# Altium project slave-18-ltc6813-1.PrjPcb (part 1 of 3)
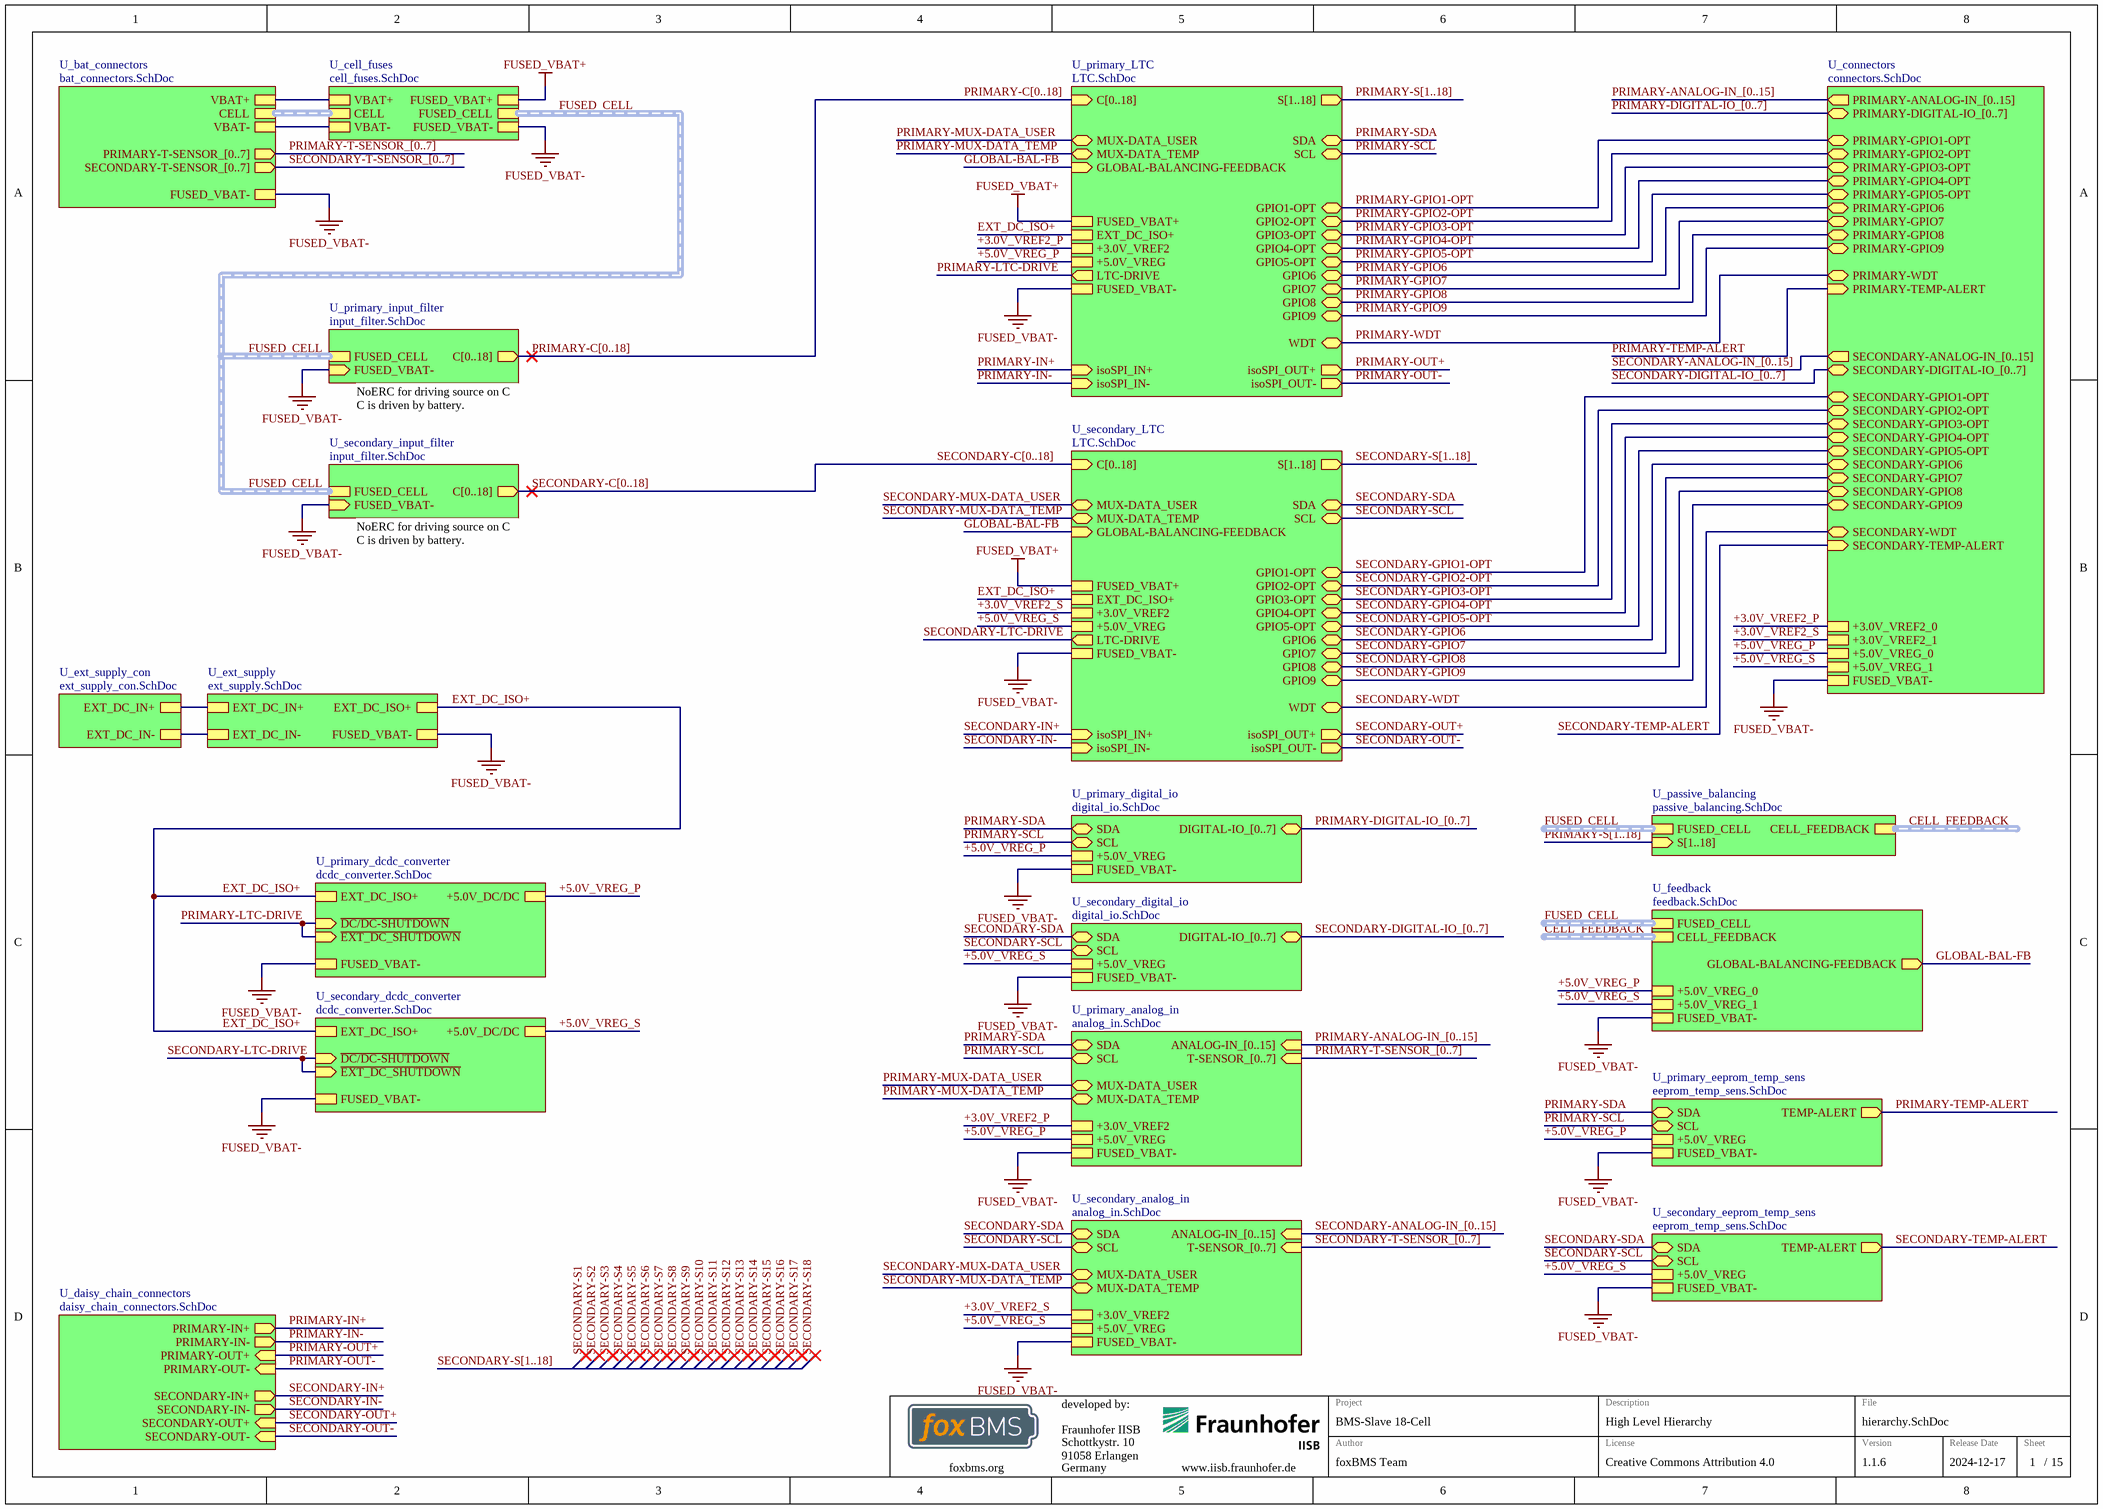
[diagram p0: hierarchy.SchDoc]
GlobalDate: 2024-12-17; GlobalLicense: Creative Commons Attribution 4.0; GlobalProject: BMS-Slave 18-Cell; GlobalVersion: 1.1.6
15 sheets, 591 parts. Net scope: strictly hierarchical (ports join the sheet entries above them; power ports are local).
Board file: slave.PcbDoc
Sheets:
  hierarchy.SchDoc
    U_cell_fuses = cell_fuses.SchDoc
    U_primary_input_filter = input_filter.SchDoc
    U_secondary_input_filter = input_filter.SchDoc
    U_ext_supply = ext_supply.SchDoc
    U_connectors = connectors.SchDoc
    U_feedback = feedback.SchDoc
    U_passive_balancing = passive_balancing.SchDoc
    U_primary_LTC = LTC.SchDoc
    U_secondary_digital_io = digital_io.SchDoc
    U_secondary_eeprom_temp_sens = eeprom_temp_sens.SchDoc
    U_secondary_analog_in = analog_in.SchDoc
    U_daisy_chain_connectors = daisy_chain_connectors.SchDoc
    U_ext_supply_con = ext_supply_con.SchDoc
    U_bat_connectors = bat_connectors.SchDoc
    U_primary_dcdc_converter = dcdc_converter.SchDoc
    U_secondary_dcdc_converter = dcdc_converter.SchDoc
    U_secondary_LTC = LTC.SchDoc
    U_primary_digital_io = digital_io.SchDoc
    U_primary_eeprom_temp_sens = eeprom_temp_sens.SchDoc
    U_primary_analog_in = analog_in.SchDoc

## Sheet hierarchy.SchDoc
size A3; SheetNumber: 1; SheetTotal: 15; SheetDescription: High Level Hierarchy

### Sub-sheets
U_bat_connectors = bat_connectors.SchDoc: CELL (harness CELL_VOLTAGES), PRIMARY-T-SENSOR_[0..7] (out), SECONDARY-T-SENSOR_[0..7] (out), VBAT+, VBAT-, FUSED_VBAT-
U_cell_fuses = cell_fuses.SchDoc: FUSED_CELL (harness CELL_VOLTAGES), CELL (harness CELL_VOLTAGES), VBAT+, VBAT-, FUSED_VBAT+, FUSED_VBAT-
U_connectors = connectors.SchDoc: PRIMARY-WDT (bidir), SECONDARY-WDT (bidir), PRIMARY-GPIO1-OPT (bidir), PRIMARY-GPIO2-OPT (bidir), PRIMARY-GPIO3-OPT (bidir), PRIMARY-GPIO4-OPT (bidir), PRIMARY-GPIO5-OPT (bidir), SECONDARY-GPIO1-OPT (bidir), SECONDARY-GPIO2-OPT (bidir), SECONDARY-GPIO3-OPT (bidir), SECONDARY-GPIO4-OPT (bidir), SECONDARY-GPIO5-OPT (bidir), PRIMARY-TEMP-ALERT (in), SECONDARY-TEMP-ALERT (in), SECONDARY-DIGITAL-IO_[0..7] (bidir), PRIMARY-DIGITAL-IO_[0..7] (bidir), PRIMARY-ANALOG-IN_[0..15] (out), SECONDARY-ANALOG-IN_[0..15] (out), PRIMARY-GPIO9 (bidir), PRIMARY-GPIO7 (bidir), PRIMARY-GPIO6 (bidir), PRIMARY-GPIO8 (bidir), SECONDARY-GPIO9 (bidir), SECONDARY-GPIO8 (bidir), SECONDARY-GPIO7 (bidir), SECONDARY-GPIO6 (bidir), +3.0V_VREF2_1, +5.0V_VREG_1, +3.0V_VREF2_0, FUSED_VBAT-, +5.0V_VREG_0
U_daisy_chain_connectors = daisy_chain_connectors.SchDoc: SECONDARY-IN+ (out), SECONDARY-IN- (out), SECONDARY-OUT+ (in), SECONDARY-OUT- (in), PRIMARY-IN+ (out), PRIMARY-IN- (out), PRIMARY-OUT- (in), PRIMARY-OUT+ (in)
U_ext_supply = ext_supply.SchDoc: EXT_DC_IN+, EXT_DC_IN-, EXT_DC_ISO+, FUSED_VBAT-
U_ext_supply_con = ext_supply_con.SchDoc: EXT_DC_IN+, EXT_DC_IN-
U_feedback = feedback.SchDoc: GLOBAL-BALANCING-FEEDBACK (out), CELL_FEEDBACK (harness CELL_FEEDBACK), FUSED_CELL (harness CELL_VOLTAGES), +5.0V_VREG_1, +5.0V_VREG_0, FUSED_VBAT-
U_passive_balancing = passive_balancing.SchDoc: FUSED_CELL (harness CELL_VOLTAGES), S[1..18] (in), CELL_FEEDBACK (harness CELL_FEEDBACK)
U_primary_analog_in = analog_in.SchDoc: MUX-DATA_TEMP (bidir), MUX-DATA_USER (bidir), ANALOG-IN_[0..15] (in), T-SENSOR_[0..7] (in), SCL (bidir), SDA (bidir), +5.0V_VREG, FUSED_VBAT-, +3.0V_VREF2
U_primary_dcdc_converter = dcdc_converter.SchDoc: +5.0V_DC/DC, FUSED_VBAT-, ~{DC/DC-SHUTDOWN} (in), EXT_DC_ISO+, ~{EXT_DC_SHUTDOWN} (in)
U_primary_digital_io = digital_io.SchDoc: SCL (bidir), SDA (bidir), DIGITAL-IO_[0..7] (bidir), +5.0V_VREG, FUSED_VBAT-
U_primary_eeprom_temp_sens = eeprom_temp_sens.SchDoc: TEMP-ALERT (out), SDA (bidir), SCL (bidir), FUSED_VBAT-, +5.0V_VREG
U_primary_input_filter = input_filter.SchDoc: FUSED_CELL (harness CELL_VOLTAGES), C[0..18] (out), FUSED_VBAT- (in)
U_primary_LTC = LTC.SchDoc: isoSPI_IN- (in), isoSPI_IN+ (in), isoSPI_OUT- (out), isoSPI_OUT+ (out), GPIO5-OPT (bidir), GPIO4-OPT (bidir), MUX-DATA_USER (bidir), GPIO1-OPT (bidir), SCL (bidir), GPIO2-OPT (bidir), MUX-DATA_TEMP (bidir), GPIO3-OPT (bidir), GLOBAL-BALANCING-FEEDBACK (in), SDA (bidir), EXT_DC_ISO+, C[0..18] (in), S[1..18] (out), WDT (bidir), GPIO8 (bidir), GPIO7 (bidir), GPIO9 (bidir), GPIO6 (bidir), FUSED_VBAT+, FUSED_VBAT-, +5.0V_VREG, +3.0V_VREF2, LTC-DRIVE (out)
U_secondary_analog_in = analog_in.SchDoc: MUX-DATA_TEMP (bidir), MUX-DATA_USER (bidir), ANALOG-IN_[0..15] (in), T-SENSOR_[0..7] (in), SCL (bidir), SDA (bidir), +5.0V_VREG, FUSED_VBAT-, +3.0V_VREF2
U_secondary_dcdc_converter = dcdc_converter.SchDoc: +5.0V_DC/DC, FUSED_VBAT-, ~{DC/DC-SHUTDOWN} (in), EXT_DC_ISO+, ~{EXT_DC_SHUTDOWN} (in)
U_secondary_digital_io = digital_io.SchDoc: SCL (bidir), SDA (bidir), DIGITAL-IO_[0..7] (bidir), +5.0V_VREG, FUSED_VBAT-
U_secondary_eeprom_temp_sens = eeprom_temp_sens.SchDoc: TEMP-ALERT (out), SDA (bidir), SCL (bidir), FUSED_VBAT-, +5.0V_VREG
U_secondary_input_filter = input_filter.SchDoc: FUSED_CELL (harness CELL_VOLTAGES), C[0..18] (out), FUSED_VBAT- (in)
U_secondary_LTC = LTC.SchDoc: isoSPI_IN- (in), isoSPI_IN+ (in), isoSPI_OUT- (out), isoSPI_OUT+ (out), GPIO5-OPT (bidir), GPIO4-OPT (bidir), MUX-DATA_USER (bidir), GPIO1-OPT (bidir), SCL (bidir), GPIO2-OPT (bidir), MUX-DATA_TEMP (bidir), GPIO3-OPT (bidir), GLOBAL-BALANCING-FEEDBACK (in), SDA (bidir), EXT_DC_ISO+, C[0..18] (in), S[1..18] (out), WDT (bidir), GPIO8 (bidir), GPIO7 (bidir), GPIO9 (bidir), GPIO6 (bidir), FUSED_VBAT+, FUSED_VBAT-, +5.0V_VREG, +3.0V_VREF2, LTC-DRIVE (out)

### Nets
+3.0V_VREF2_P: sheet U_connectors/+3.0V_VREF2_0, sheet U_primary_LTC/+3.0V_VREF2, sheet U_primary_analog_in/+3.0V_VREF2  [project net +3.0V_VREF2]
+3.0V_VREF2_S: sheet U_connectors/+3.0V_VREF2_1, sheet U_secondary_analog_in/+3.0V_VREF2, sheet U_secondary_LTC/+3.0V_VREF2  [project net +3.0V_VREF2]
+5.0V_VREG_P: sheet U_connectors/+5.0V_VREG_0, sheet U_feedback/+5.0V_VREG_0, sheet U_primary_LTC/+5.0V_VREG, sheet U_primary_dcdc_converter/+5.0V_DC/DC, sheet U_primary_digital_io/+5.0V_VREG, sheet U_primary_eeprom_temp_sens/+5.0V_VREG, sheet U_primary_analog_in/+5.0V_VREG  [project net +5.0V_VREG]
+5.0V_VREG_S: sheet U_connectors/+5.0V_VREG_1, sheet U_feedback/+5.0V_VREG_1, sheet U_secondary_digital_io/+5.0V_VREG, sheet U_secondary_eeprom_temp_sens/+5.0V_VREG, sheet U_secondary_analog_in/+5.0V_VREG, sheet U_secondary_dcdc_converter/+5.0V_DC/DC, sheet U_secondary_LTC/+5.0V_VREG  [project net +5.0V_VREG]
FUSED_VBAT+: sheet U_cell_fuses/FUSED_VBAT+, sheet U_primary_LTC/FUSED_VBAT+, sheet U_secondary_LTC/FUSED_VBAT+
FUSED_VBAT-: sheet U_cell_fuses/FUSED_VBAT-, sheet U_primary_input_filter/FUSED_VBAT-, sheet U_secondary_input_filter/FUSED_VBAT-, sheet U_ext_supply/FUSED_VBAT-, sheet U_connectors/FUSED_VBAT-, sheet U_feedback/FUSED_VBAT-, sheet U_primary_LTC/FUSED_VBAT-, sheet U_secondary_digital_io/FUSED_VBAT-, sheet U_secondary_eeprom_temp_sens/FUSED_VBAT-, sheet U_secondary_analog_in/FUSED_VBAT-, sheet U_bat_connectors/FUSED_VBAT-, sheet U_primary_dcdc_converter/FUSED_VBAT-, sheet U_secondary_dcdc_converter/FUSED_VBAT-, sheet U_secondary_LTC/FUSED_VBAT-, sheet U_primary_digital_io/FUSED_VBAT-, sheet U_primary_eeprom_temp_sens/FUSED_VBAT-, sheet U_primary_analog_in/FUSED_VBAT-
VBAT+: sheet U_cell_fuses/VBAT+, sheet U_bat_connectors/VBAT+
VBAT-: sheet U_cell_fuses/VBAT-, sheet U_bat_connectors/VBAT-
EXT_DC_IN+: sheet U_ext_supply/EXT_DC_IN+, sheet U_ext_supply_con/EXT_DC_IN+
EXT_DC_IN-: sheet U_ext_supply/EXT_DC_IN-, sheet U_ext_supply_con/EXT_DC_IN-
EXT_DC_ISO+: sheet U_ext_supply/EXT_DC_ISO+, sheet U_primary_LTC/EXT_DC_ISO+, sheet U_primary_dcdc_converter/EXT_DC_ISO+, sheet U_secondary_dcdc_converter/EXT_DC_ISO+, sheet U_secondary_LTC/EXT_DC_ISO+
GLOBAL-BAL-FB: sheet U_feedback/GLOBAL-BALANCING-FEEDBACK, sheet U_primary_LTC/GLOBAL-BALANCING-FEEDBACK, sheet U_secondary_LTC/GLOBAL-BALANCING-FEEDBACK
PRIMARY-GPIO1-OPT: sheet U_connectors/PRIMARY-GPIO1-OPT, sheet U_primary_LTC/GPIO1-OPT
PRIMARY-GPIO2-OPT: sheet U_connectors/PRIMARY-GPIO2-OPT, sheet U_primary_LTC/GPIO2-OPT
PRIMARY-GPIO3-OPT: sheet U_connectors/PRIMARY-GPIO3-OPT, sheet U_primary_LTC/GPIO3-OPT
PRIMARY-GPIO4-OPT: sheet U_connectors/PRIMARY-GPIO4-OPT, sheet U_primary_LTC/GPIO4-OPT
PRIMARY-GPIO5-OPT: sheet U_connectors/PRIMARY-GPIO5-OPT, sheet U_primary_LTC/GPIO5-OPT
PRIMARY-GPIO6: sheet U_connectors/PRIMARY-GPIO6, sheet U_primary_LTC/GPIO6
PRIMARY-GPIO7: sheet U_connectors/PRIMARY-GPIO7, sheet U_primary_LTC/GPIO7
PRIMARY-GPIO8: sheet U_connectors/PRIMARY-GPIO8, sheet U_primary_LTC/GPIO8
PRIMARY-GPIO9: sheet U_connectors/PRIMARY-GPIO9, sheet U_primary_LTC/GPIO9
PRIMARY-IN+: sheet U_primary_LTC/isoSPI_IN+, sheet U_daisy_chain_connectors/PRIMARY-IN+
PRIMARY-IN-: sheet U_primary_LTC/isoSPI_IN-, sheet U_daisy_chain_connectors/PRIMARY-IN-
PRIMARY-LTC-DRIVE: sheet U_primary_LTC/LTC-DRIVE, sheet U_primary_dcdc_converter/~{DC/DC-SHUTDOWN}, sheet U_primary_dcdc_converter/~{EXT_DC_SHUTDOWN}
PRIMARY-MUX-DATA_TEMP: sheet U_primary_LTC/MUX-DATA_TEMP, sheet U_primary_analog_in/MUX-DATA_TEMP
PRIMARY-MUX-DATA_USER: sheet U_primary_LTC/MUX-DATA_USER, sheet U_primary_analog_in/MUX-DATA_USER
PRIMARY-OUT+: sheet U_primary_LTC/isoSPI_OUT+, sheet U_daisy_chain_connectors/PRIMARY-OUT+
PRIMARY-OUT-: sheet U_primary_LTC/isoSPI_OUT-, sheet U_daisy_chain_connectors/PRIMARY-OUT-
PRIMARY-SCL: sheet U_primary_LTC/SCL, sheet U_primary_digital_io/SCL, sheet U_primary_eeprom_temp_sens/SCL, sheet U_primary_analog_in/SCL
PRIMARY-SDA: sheet U_primary_LTC/SDA, sheet U_primary_digital_io/SDA, sheet U_primary_eeprom_temp_sens/SDA, sheet U_primary_analog_in/SDA
PRIMARY-TEMP-ALERT: sheet U_connectors/PRIMARY-TEMP-ALERT, sheet U_primary_eeprom_temp_sens/TEMP-ALERT
PRIMARY-WDT: sheet U_connectors/PRIMARY-WDT, sheet U_primary_LTC/WDT
SECONDARY-GPIO1-OPT: sheet U_connectors/SECONDARY-GPIO1-OPT, sheet U_secondary_LTC/GPIO1-OPT
SECONDARY-GPIO2-OPT: sheet U_connectors/SECONDARY-GPIO2-OPT, sheet U_secondary_LTC/GPIO2-OPT
SECONDARY-GPIO3-OPT: sheet U_connectors/SECONDARY-GPIO3-OPT, sheet U_secondary_LTC/GPIO3-OPT
SECONDARY-GPIO4-OPT: sheet U_connectors/SECONDARY-GPIO4-OPT, sheet U_secondary_LTC/GPIO4-OPT
SECONDARY-GPIO5-OPT: sheet U_connectors/SECONDARY-GPIO5-OPT, sheet U_secondary_LTC/GPIO5-OPT
SECONDARY-GPIO6: sheet U_connectors/SECONDARY-GPIO6, sheet U_secondary_LTC/GPIO6
SECONDARY-GPIO7: sheet U_connectors/SECONDARY-GPIO7, sheet U_secondary_LTC/GPIO7
SECONDARY-GPIO8: sheet U_connectors/SECONDARY-GPIO8, sheet U_secondary_LTC/GPIO8
SECONDARY-GPIO9: sheet U_connectors/SECONDARY-GPIO9, sheet U_secondary_LTC/GPIO9
SECONDARY-IN+: sheet U_daisy_chain_connectors/SECONDARY-IN+, sheet U_secondary_LTC/isoSPI_IN+
SECONDARY-IN-: sheet U_daisy_chain_connectors/SECONDARY-IN-, sheet U_secondary_LTC/isoSPI_IN-
SECONDARY-LTC-DRIVE: sheet U_secondary_dcdc_converter/~{DC/DC-SHUTDOWN}, sheet U_secondary_dcdc_converter/~{EXT_DC_SHUTDOWN}, sheet U_secondary_LTC/LTC-DRIVE
SECONDARY-MUX-DATA_TEMP: sheet U_secondary_analog_in/MUX-DATA_TEMP, sheet U_secondary_LTC/MUX-DATA_TEMP
SECONDARY-MUX-DATA_USER: sheet U_secondary_analog_in/MUX-DATA_USER, sheet U_secondary_LTC/MUX-DATA_USER
SECONDARY-OUT+: sheet U_daisy_chain_connectors/SECONDARY-OUT+, sheet U_secondary_LTC/isoSPI_OUT+
SECONDARY-OUT-: sheet U_daisy_chain_connectors/SECONDARY-OUT-, sheet U_secondary_LTC/isoSPI_OUT-
SECONDARY-SCL: sheet U_secondary_digital_io/SCL, sheet U_secondary_eeprom_temp_sens/SCL, sheet U_secondary_analog_in/SCL, sheet U_secondary_LTC/SCL
SECONDARY-SDA: sheet U_secondary_digital_io/SDA, sheet U_secondary_eeprom_temp_sens/SDA, sheet U_secondary_analog_in/SDA, sheet U_secondary_LTC/SDA
SECONDARY-TEMP-ALERT: sheet U_connectors/SECONDARY-TEMP-ALERT, sheet U_secondary_eeprom_temp_sens/TEMP-ALERT
SECONDARY-WDT: sheet U_connectors/SECONDARY-WDT, sheet U_secondary_LTC/WDT

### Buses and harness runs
bus PRIMARY-ANALOG-IN_[0..15] = sheet U_connectors/PRIMARY-ANALOG-IN_[0..15]
bus PRIMARY-ANALOG-IN_[0..15] = sheet U_primary_analog_in/ANALOG-IN_[0..15]
bus PRIMARY-C[0..18] = sheet U_primary_input_filter/C[0..18] = sheet U_primary_LTC/C[0..18]
bus PRIMARY-DIGITAL-IO_[0..7] = sheet U_connectors/PRIMARY-DIGITAL-IO_[0..7]
bus PRIMARY-DIGITAL-IO_[0..7] = sheet U_primary_digital_io/DIGITAL-IO_[0..7]
bus PRIMARY-S[1..18] = sheet U_passive_balancing/S[1..18]
bus PRIMARY-S[1..18] = sheet U_primary_LTC/S[1..18]
bus PRIMARY-T-SENSOR_[0..7] = sheet U_bat_connectors/PRIMARY-T-SENSOR_[0..7]
bus PRIMARY-T-SENSOR_[0..7] = sheet U_primary_analog_in/T-SENSOR_[0..7]
bus SECONDARY-ANALOG-IN_[0..15] = sheet U_connectors/SECONDARY-ANALOG-IN_[0..15]
bus SECONDARY-ANALOG-IN_[0..15] = sheet U_secondary_analog_in/ANALOG-IN_[0..15]
bus SECONDARY-C[0..18] = sheet U_secondary_input_filter/C[0..18] = sheet U_secondary_LTC/C[0..18]
bus SECONDARY-DIGITAL-IO_[0..7] = sheet U_connectors/SECONDARY-DIGITAL-IO_[0..7]
bus SECONDARY-DIGITAL-IO_[0..7] = sheet U_secondary_digital_io/DIGITAL-IO_[0..7]
bus SECONDARY-S[1..18]
bus SECONDARY-S[1..18] = sheet U_secondary_LTC/S[1..18]
bus SECONDARY-T-SENSOR_[0..7] = sheet U_bat_connectors/SECONDARY-T-SENSOR_[0..7]
bus SECONDARY-T-SENSOR_[0..7] = sheet U_secondary_analog_in/T-SENSOR_[0..7]
harness CELL_FEEDBACK = sheet U_feedback/CELL_FEEDBACK
harness CELL_FEEDBACK = sheet U_passive_balancing/CELL_FEEDBACK
harness FUSED_CELL = sheet U_cell_fuses/FUSED_CELL = sheet U_primary_input_filter/FUSED_CELL = sheet U_secondary_input_filter/FUSED_CELL
harness FUSED_CELL = sheet U_feedback/FUSED_CELL
harness FUSED_CELL = sheet U_passive_balancing/FUSED_CELL
harness sheet U_bat_connectors/CELL = sheet U_cell_fuses/CELL

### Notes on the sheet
- NoERC for driving source on C
  C is driven by battery.
- Labels drawn without touching a wire or pin: SECONDARY-S1, SECONDARY-S2, SECONDARY-S3, SECONDARY-S4, SECONDARY-S5, SECONDARY-S6, SECONDARY-S7, SECONDARY-S8, SECONDARY-S9, SECONDARY-S10, SECONDARY-S11, SECONDARY-S12, SECONDARY-S13, SECONDARY-S14, SECONDARY-S15, SECONDARY-S16, SECONDARY-S17, SECONDARY-S18

## Sheet cell_fuses.SchDoc
size A3; SheetNumber: 3; SheetTotal: 15; SheetDescription: Cell Fuses
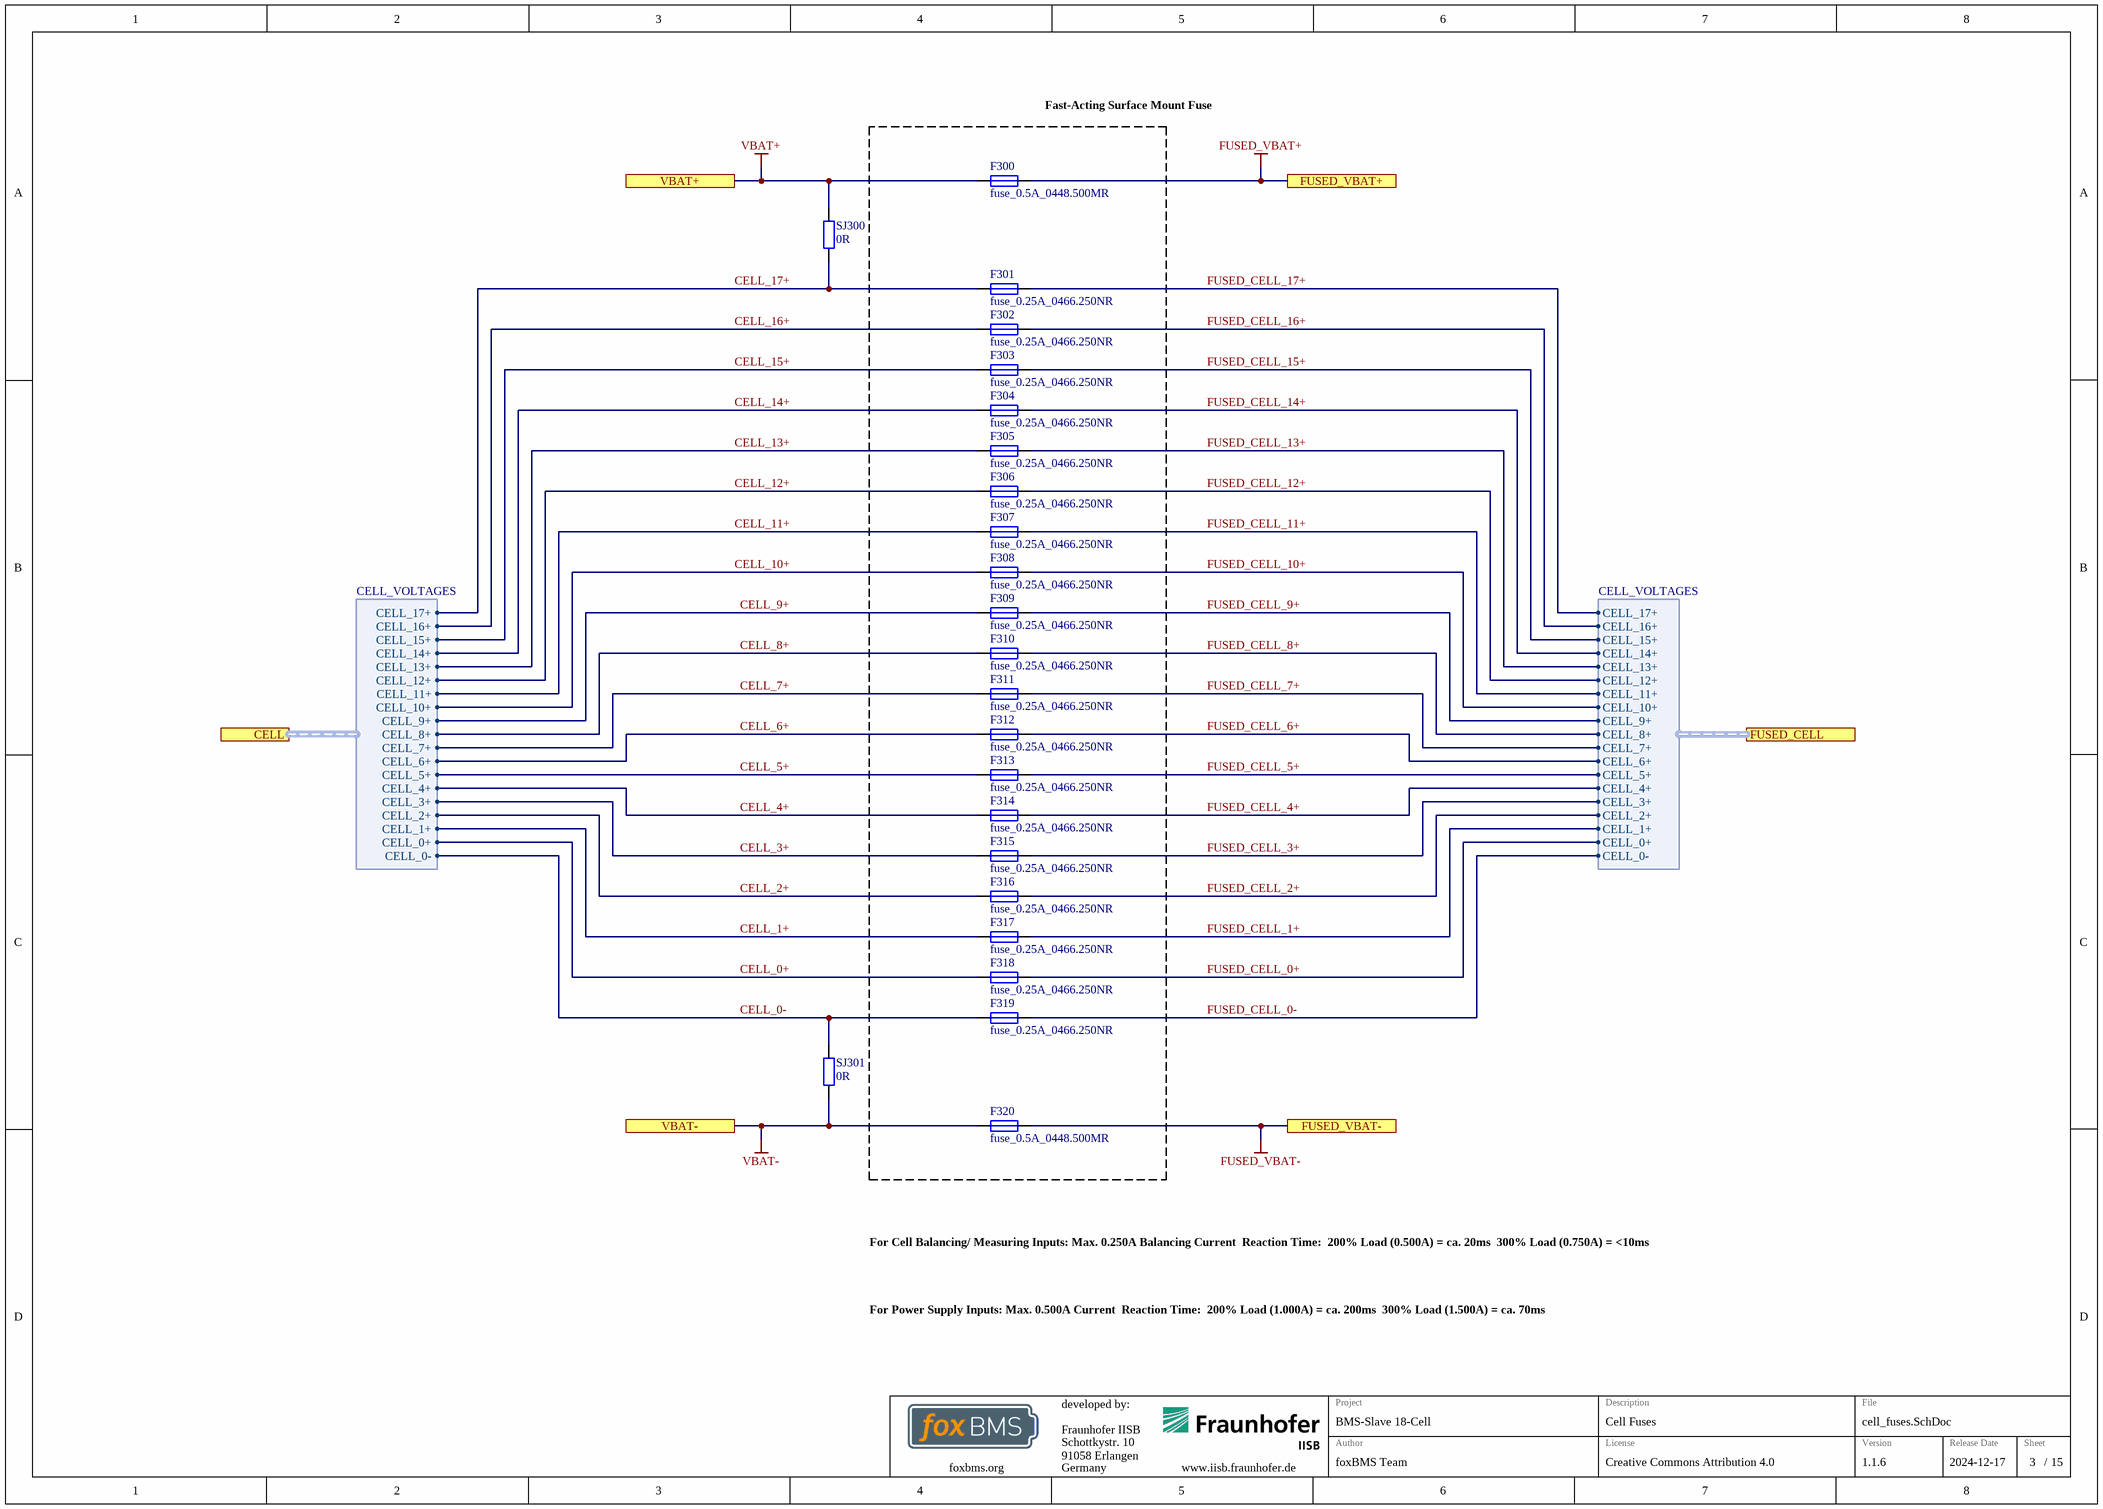
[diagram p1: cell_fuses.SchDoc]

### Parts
F300  fuse_0.5A_0448.500MR  [LITTLEFUSE_448]
F301  fuse_0.25A_0466.250NR  [LITTLEFUSE_466]
F302  fuse_0.25A_0466.250NR  [LITTLEFUSE_466]
F303  fuse_0.25A_0466.250NR  [LITTLEFUSE_466]
F304  fuse_0.25A_0466.250NR  [LITTLEFUSE_466]
F305  fuse_0.25A_0466.250NR  [LITTLEFUSE_466]
F306  fuse_0.25A_0466.250NR  [LITTLEFUSE_466]
F307  fuse_0.25A_0466.250NR  [LITTLEFUSE_466]
F308  fuse_0.25A_0466.250NR  [LITTLEFUSE_466]
F309  fuse_0.25A_0466.250NR  [LITTLEFUSE_466]
F310  fuse_0.25A_0466.250NR  [LITTLEFUSE_466]
F311  fuse_0.25A_0466.250NR  [LITTLEFUSE_466]
F312  fuse_0.25A_0466.250NR  [LITTLEFUSE_466]
F313  fuse_0.25A_0466.250NR  [LITTLEFUSE_466]
F314  fuse_0.25A_0466.250NR  [LITTLEFUSE_466]
F315  fuse_0.25A_0466.250NR  [LITTLEFUSE_466]
F316  fuse_0.25A_0466.250NR  [LITTLEFUSE_466]
F317  fuse_0.25A_0466.250NR  [LITTLEFUSE_466]
F318  fuse_0.25A_0466.250NR  [LITTLEFUSE_466]
F319  fuse_0.25A_0466.250NR  [LITTLEFUSE_466]
F320  fuse_0.5A_0448.500MR  [LITTLEFUSE_448]
SJ300  0R  [RESC1608X05N]
SJ301  0R  [RESC1608X05N]

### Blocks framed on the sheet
Fast-Acting Surface Mount Fuse: F300-F320

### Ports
CELL (harness CELL_VOLTAGES), FUSED_CELL (harness CELL_VOLTAGES), FUSED_VBAT+, FUSED_VBAT-, VBAT+, VBAT-

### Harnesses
CELL_VOLTAGES: CELL_0-, CELL_0+, CELL_1+, CELL_10+, CELL_11+, CELL_12+, CELL_13+, CELL_14+, CELL_15+, CELL_16+, CELL_17+, CELL_2+, CELL_3+, CELL_4+, CELL_5+, CELL_6+, CELL_7+, CELL_8+, CELL_9+

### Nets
FUSED_VBAT+: F300.2 ; port FUSED_VBAT+
FUSED_VBAT-: F320.2 ; port FUSED_VBAT-
VBAT+: F300.1 SJ300.1 ; port VBAT+
VBAT-: F320.1 SJ301.2 ; port VBAT-
CELL_0+: F318.1 ; port CELL.CELL_0+
CELL_0-: F319.1 SJ301.1 ; port CELL.CELL_0-
CELL_1+: F317.1 ; port CELL.CELL_1+
CELL_2+: F316.1 ; port CELL.CELL_2+
CELL_3+: F315.1 ; port CELL.CELL_3+
CELL_4+: F314.1 ; port CELL.CELL_4+
CELL_5+: F313.1 ; port CELL.CELL_5+
CELL_6+: F312.1 ; port CELL.CELL_6+
CELL_7+: F311.1 ; port CELL.CELL_7+
CELL_8+: F310.1 ; port CELL.CELL_8+
CELL_9+: F309.1 ; port CELL.CELL_9+
CELL_10+: F308.1 ; port CELL.CELL_10+
CELL_11+: F307.1 ; port CELL.CELL_11+
CELL_12+: F306.1 ; port CELL.CELL_12+
CELL_13+: F305.1 ; port CELL.CELL_13+
CELL_14+: F304.1 ; port CELL.CELL_14+
CELL_15+: F303.1 ; port CELL.CELL_15+
CELL_16+: F302.1 ; port CELL.CELL_16+
CELL_17+: F301.1 SJ300.2 ; port CELL.CELL_17+
FUSED_CELL_0+: F318.2 ; port FUSED_CELL.CELL_0+  [project net FUSED_CELL.CELL_0+]
FUSED_CELL_0-: F319.2 ; port FUSED_CELL.CELL_0-  [project net FUSED_CELL.CELL_0-]
FUSED_CELL_1+: F317.2 ; port FUSED_CELL.CELL_1+  [project net FUSED_CELL.CELL_1+]
FUSED_CELL_2+: F316.2 ; port FUSED_CELL.CELL_2+  [project net FUSED_CELL.CELL_2+]
FUSED_CELL_3+: F315.2 ; port FUSED_CELL.CELL_3+  [project net FUSED_CELL.CELL_3+]
FUSED_CELL_4+: F314.2 ; port FUSED_CELL.CELL_4+  [project net FUSED_CELL.CELL_4+]
FUSED_CELL_5+: F313.2 ; port FUSED_CELL.CELL_5+  [project net FUSED_CELL.CELL_5+]
FUSED_CELL_6+: F312.2 ; port FUSED_CELL.CELL_6+  [project net FUSED_CELL.CELL_6+]
FUSED_CELL_7+: F311.2 ; port FUSED_CELL.CELL_7+  [project net FUSED_CELL.CELL_7+]
FUSED_CELL_8+: F310.2 ; port FUSED_CELL.CELL_8+  [project net FUSED_CELL.CELL_8+]
FUSED_CELL_9+: F309.2 ; port FUSED_CELL.CELL_9+  [project net FUSED_CELL.CELL_9+]
FUSED_CELL_10+: F308.2 ; port FUSED_CELL.CELL_10+  [project net FUSED_CELL.CELL_10+]
FUSED_CELL_11+: F307.2 ; port FUSED_CELL.CELL_11+  [project net FUSED_CELL.CELL_11+]
FUSED_CELL_12+: F306.2 ; port FUSED_CELL.CELL_12+  [project net FUSED_CELL.CELL_12+]
FUSED_CELL_13+: F305.2 ; port FUSED_CELL.CELL_13+  [project net FUSED_CELL.CELL_13+]
FUSED_CELL_14+: F304.2 ; port FUSED_CELL.CELL_14+  [project net FUSED_CELL.CELL_14+]
FUSED_CELL_15+: F303.2 ; port FUSED_CELL.CELL_15+  [project net FUSED_CELL.CELL_15+]
FUSED_CELL_16+: F302.2 ; port FUSED_CELL.CELL_16+  [project net FUSED_CELL.CELL_16+]
FUSED_CELL_17+: F301.2 ; port FUSED_CELL.CELL_17+  [project net FUSED_CELL.CELL_17+]

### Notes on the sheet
- For Cell Balancing/ Measuring Inputs: Max. 0.250A Balancing Current
  Reaction Time:
  200% Load (0.500A) = ca. 20ms
  300% Load (0.750A) = <10ms
- For Power Supply Inputs: Max. 0.500A Current
  Reaction Time:
  200% Load (1.000A) = ca. 200ms
  300% Load (1.500A) = ca. 70ms

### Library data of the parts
F300 F320 = fuse_0.5A_0448.500MR: Fuse, Surface Mount, NANO2 Series, 500 mA, 125 VAC, 32 VDC, Very Fast Acting, SMD; Manufacturer: Littlefuse; Automotive Qualified: False
F301-F319 = fuse_0.25A_0466.250NR: Fuse, Surface Mount, 466 Series, 250 mA, 125 VAC, 125 VDC, Very Fast Acting, 1206; Manufacturer: Littlefuse; Automotive Qualified: False
SJ300 SJ301 = gen_R_0R_0603: SMD Resistor 0R 0603; Power: 0.1W; Case EIA: 0603; Case Metric: 1608; Maximum Working Voltage: 75V; PnP Package: R_0603; Automotive Qualified: True

## Sheet input_filter.SchDoc
size A3; SheetNumber: 4; SheetTotal: 15; SheetDescription: Input Filter
Used 2 times, as channels U_primary_input_filter, U_secondary_input_filter. Parts and nets are listed once, with the designators drawn on the sheet.
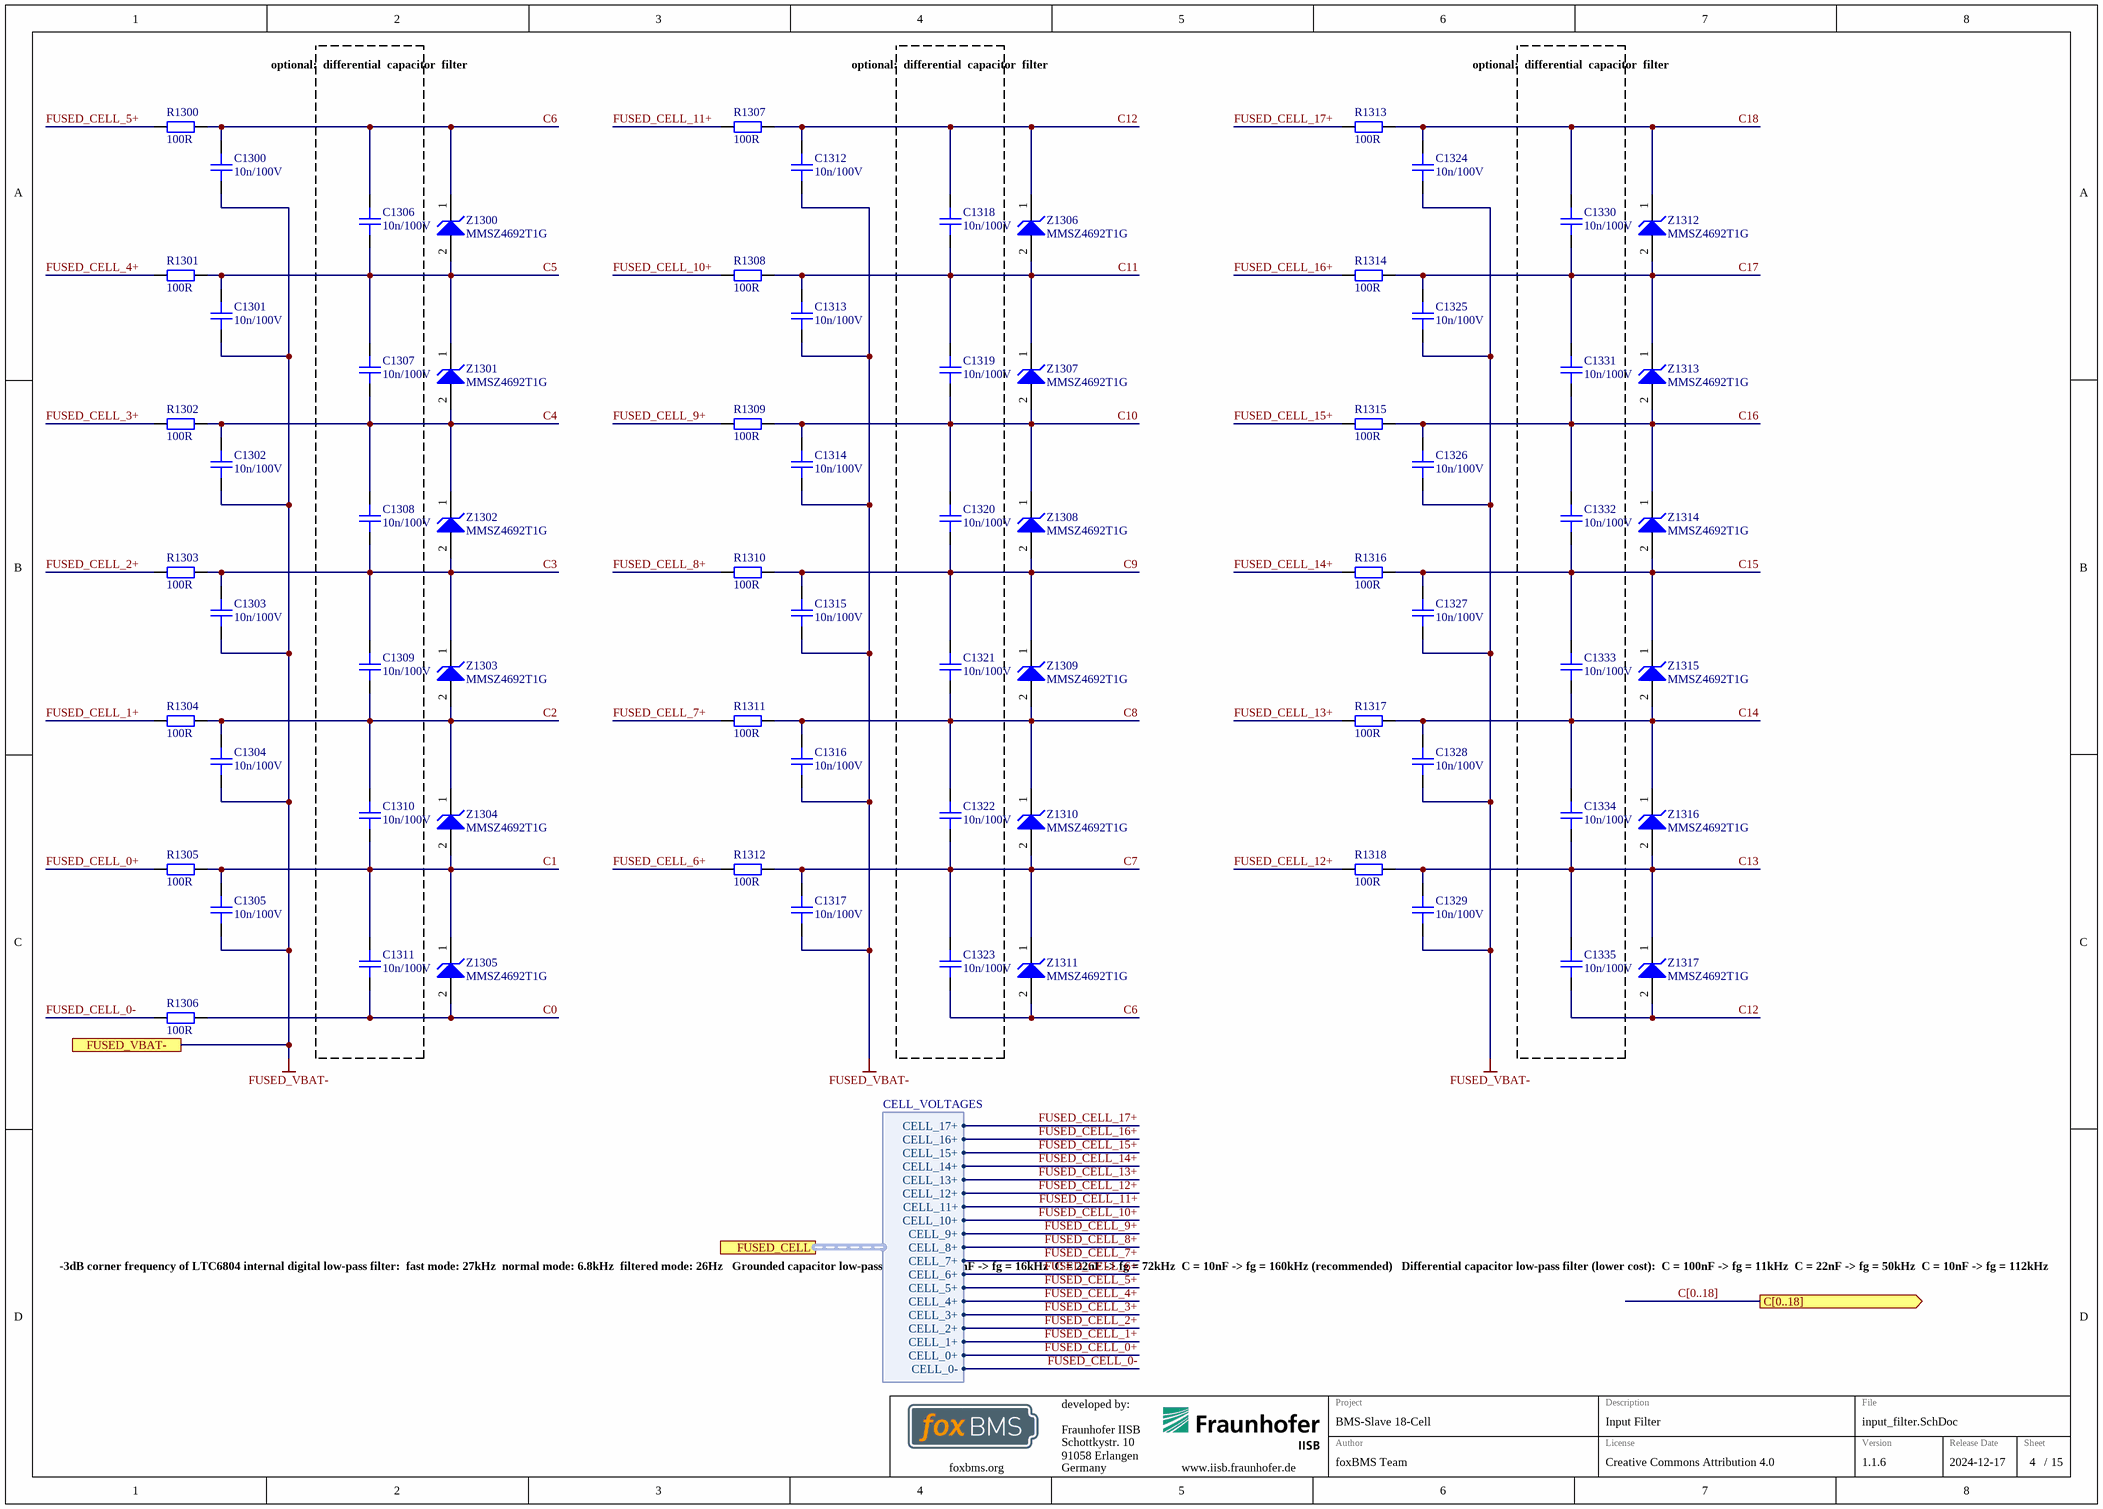
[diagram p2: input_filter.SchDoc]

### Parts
C1300  10n/100V  [CAPC1608X08N]
C1301  10n/100V  [CAPC1608X08N]
C1302  10n/100V  [CAPC1608X08N]
C1303  10n/100V  [CAPC1608X08N]
C1304  10n/100V  [CAPC1608X08N]
C1305  10n/100V  [CAPC1608X08N]
C1306  10n/100V  [CAPC1608X08N]
C1307  10n/100V  [CAPC1608X08N]
C1308  10n/100V  [CAPC1608X08N]
C1309  10n/100V  [CAPC1608X08N]
C1310  10n/100V  [CAPC1608X08N]
C1311  10n/100V  [CAPC1608X08N]
C1312  10n/100V  [CAPC1608X08N]
C1313  10n/100V  [CAPC1608X08N]
C1314  10n/100V  [CAPC1608X08N]
C1315  10n/100V  [CAPC1608X08N]
C1316  10n/100V  [CAPC1608X08N]
C1317  10n/100V  [CAPC1608X08N]
C1318  10n/100V  [CAPC1608X08N]
C1319  10n/100V  [CAPC1608X08N]
C1320  10n/100V  [CAPC1608X08N]
C1321  10n/100V  [CAPC1608X08N]
C1322  10n/100V  [CAPC1608X08N]
C1323  10n/100V  [CAPC1608X08N]
C1324  10n/100V  [CAPC1608X08N]
C1325  10n/100V  [CAPC1608X08N]
C1326  10n/100V  [CAPC1608X08N]
C1327  10n/100V  [CAPC1608X08N]
C1328  10n/100V  [CAPC1608X08N]
C1329  10n/100V  [CAPC1608X08N]
C1330  10n/100V  [CAPC1608X08N]
C1331  10n/100V  [CAPC1608X08N]
C1332  10n/100V  [CAPC1608X08N]
C1333  10n/100V  [CAPC1608X08N]
C1334  10n/100V  [CAPC1608X08N]
C1335  10n/100V  [CAPC1608X08N]
R1300  100R  [RESC1608X05N]
R1301  100R  [RESC1608X05N]
R1302  100R  [RESC1608X05N]
R1303  100R  [RESC1608X05N]
R1304  100R  [RESC1608X05N]
R1305  100R  [RESC1608X05N]
R1306  100R  [RESC1608X05N]
R1307  100R  [RESC1608X05N]
R1308  100R  [RESC1608X05N]
R1309  100R  [RESC1608X05N]
R1310  100R  [RESC1608X05N]
R1311  100R  [RESC1608X05N]
R1312  100R  [RESC1608X05N]
R1313  100R  [RESC1608X05N]
R1314  100R  [RESC1608X05N]
R1315  100R  [RESC1608X05N]
R1316  100R  [RESC1608X05N]
R1317  100R  [RESC1608X05N]
R1318  100R  [RESC1608X05N]
Z1300  MMSZ4692T1G  [ONSC-SOD-123-2-425-04_V]
Z1301  MMSZ4692T1G  [ONSC-SOD-123-2-425-04_V]
Z1302  MMSZ4692T1G  [ONSC-SOD-123-2-425-04_V]
Z1303  MMSZ4692T1G  [ONSC-SOD-123-2-425-04_V]
Z1304  MMSZ4692T1G  [ONSC-SOD-123-2-425-04_V]
Z1305  MMSZ4692T1G  [ONSC-SOD-123-2-425-04_V]
Z1306  MMSZ4692T1G  [ONSC-SOD-123-2-425-04_V]
Z1307  MMSZ4692T1G  [ONSC-SOD-123-2-425-04_V]
Z1308  MMSZ4692T1G  [ONSC-SOD-123-2-425-04_V]
Z1309  MMSZ4692T1G  [ONSC-SOD-123-2-425-04_V]
Z1310  MMSZ4692T1G  [ONSC-SOD-123-2-425-04_V]
Z1311  MMSZ4692T1G  [ONSC-SOD-123-2-425-04_V]
Z1312  MMSZ4692T1G  [ONSC-SOD-123-2-425-04_V]
Z1313  MMSZ4692T1G  [ONSC-SOD-123-2-425-04_V]
Z1314  MMSZ4692T1G  [ONSC-SOD-123-2-425-04_V]
Z1315  MMSZ4692T1G  [ONSC-SOD-123-2-425-04_V]
Z1316  MMSZ4692T1G  [ONSC-SOD-123-2-425-04_V]
Z1317  MMSZ4692T1G  [ONSC-SOD-123-2-425-04_V]

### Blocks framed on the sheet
optional: / differential / capacitor / filter: C1306-C1311
optional: / differential / capacitor / filter: C1318-C1323
optional: / differential / capacitor / filter: C1330-C1335

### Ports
C[0..18] (out), FUSED_CELL (harness CELL_VOLTAGES), FUSED_VBAT-

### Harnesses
CELL_VOLTAGES: CELL_0-, CELL_0+, CELL_1+, CELL_10+, CELL_11+, CELL_12+, CELL_13+, CELL_14+, CELL_15+, CELL_16+, CELL_17+, CELL_2+, CELL_3+, CELL_4+, CELL_5+, CELL_6+, CELL_7+, CELL_8+, CELL_9+

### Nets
FUSED_VBAT-: C1300.2 C1301.2 C1302.2 C1303.2 C1304.2 C1305.2 C1312.2 C1313.2 C1314.2 C1315.2 C1316.2 C1317.2 C1324.2 C1325.2 C1326.2 C1327.2 C1328.2 C1329.2 ; port FUSED_VBAT-
C0: C1311.2 R1306.2 Z1305.2(A)
C1: C1305.1 C1310.2 C1311.1 R1305.2 Z1304.2(A) Z1305.1(K)
C2: C1304.1 C1309.2 C1310.1 R1304.2 Z1303.2(A) Z1304.1(K)
C3: C1303.1 C1308.2 C1309.1 R1303.2 Z1302.2(A) Z1303.1(K)
C4: C1302.1 C1307.2 C1308.1 R1302.2 Z1301.2(A) Z1302.1(K)
C5: C1301.1 C1306.2 C1307.1 R1301.2 Z1300.2(A) Z1301.1(K)
C6: C1300.1 C1306.1 C1323.2 R1300.2 Z1300.1(K) Z1311.2(A)
C7: C1317.1 C1322.2 C1323.1 R1312.2 Z1310.2(A) Z1311.1(K)
C8: C1316.1 C1321.2 C1322.1 R1311.2 Z1309.2(A) Z1310.1(K)
C9: C1315.1 C1320.2 C1321.1 R1310.2 Z1308.2(A) Z1309.1(K)
C10: C1314.1 C1319.2 C1320.1 R1309.2 Z1307.2(A) Z1308.1(K)
C11: C1313.1 C1318.2 C1319.1 R1308.2 Z1306.2(A) Z1307.1(K)
C12: C1312.1 C1318.1 C1335.2 R1307.2 Z1306.1(K) Z1317.2(A)
C13: C1329.1 C1334.2 C1335.1 R1318.2 Z1316.2(A) Z1317.1(K)
C14: C1328.1 C1333.2 C1334.1 R1317.2 Z1315.2(A) Z1316.1(K)
C15: C1327.1 C1332.2 C1333.1 R1316.2 Z1314.2(A) Z1315.1(K)
C16: C1326.1 C1331.2 C1332.1 R1315.2 Z1313.2(A) Z1314.1(K)
C17: C1325.1 C1330.2 C1331.1 R1314.2 Z1312.2(A) Z1313.1(K)
C18: C1324.1 C1330.1 R1313.2 Z1312.1(K)
FUSED_CELL_0+: R1305.1 ; port FUSED_CELL.CELL_0+
FUSED_CELL_0-: R1306.1 ; port FUSED_CELL.CELL_0-
FUSED_CELL_1+: R1304.1 ; port FUSED_CELL.CELL_1+
FUSED_CELL_2+: R1303.1 ; port FUSED_CELL.CELL_2+
FUSED_CELL_3+: R1302.1 ; port FUSED_CELL.CELL_3+
FUSED_CELL_4+: R1301.1 ; port FUSED_CELL.CELL_4+
FUSED_CELL_5+: R1300.1 ; port FUSED_CELL.CELL_5+
FUSED_CELL_6+: R1312.1 ; port FUSED_CELL.CELL_6+
FUSED_CELL_7+: R1311.1 ; port FUSED_CELL.CELL_7+
FUSED_CELL_8+: R1310.1 ; port FUSED_CELL.CELL_8+
FUSED_CELL_9+: R1309.1 ; port FUSED_CELL.CELL_9+
FUSED_CELL_10+: R1308.1 ; port FUSED_CELL.CELL_10+
FUSED_CELL_11+: R1307.1 ; port FUSED_CELL.CELL_11+
FUSED_CELL_12+: R1318.1 ; port FUSED_CELL.CELL_12+
FUSED_CELL_13+: R1317.1 ; port FUSED_CELL.CELL_13+
FUSED_CELL_14+: R1316.1 ; port FUSED_CELL.CELL_14+
FUSED_CELL_15+: R1315.1 ; port FUSED_CELL.CELL_15+
FUSED_CELL_16+: R1314.1 ; port FUSED_CELL.CELL_16+
FUSED_CELL_17+: R1313.1 ; port FUSED_CELL.CELL_17+

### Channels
U_primary_input_filter: designators end in _1; ports FUSED_VBAT-=FUSED_VBAT-
U_secondary_input_filter: designators end in _2; ports FUSED_VBAT-=FUSED_VBAT-

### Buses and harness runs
bus C[0..18] = port C[0..18]

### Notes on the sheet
- -3dB corner frequency of LTC6804 internal digital low-pass filter:
  fast mode: 27kHz
  normal mode: 6.8kHz
  filtered mode: 26Hz
  Grounded capacitor low-pass filter:
  C = 100nF -> fg = 16kHz
  C = 22nF -> fg = 72kHz
  C = 10nF -> fg = 160kHz (recommended)
  Differential capacitor low-pass filter (lower cost):
  C = 100nF -> fg = 11kHz
  C = 22nF -> fg = 50kHz
  C = 10nF -> fg = 112kHz

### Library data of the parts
C1300-C1335 = gen_C_ceramic_10n_100V_X7R_0603: MLCC; Capacitance: 10n; Rated Voltage: 100V; Dielectric: X7R; Case EIA: 0603; Case Metric: 1608; Automotive Qualified: True
R1300-R1318 = gen_R_100R_0603: SMD Resistor 100R 0603; Tolerance: 1%; Power: 0.1W; Case EIA: 0603; Case Metric: 1608; Maximum Working Voltage: 75V; PnP Package: R_0603; Automotive Qualified: True
Z1300-Z1317 = CMP-1060-00434-1: Zener Voltage Regulator, 500 mW, 2-Pin SOD-123, Pb-Free, Tape and Reel; Manufacturer: On Semiconductor; VZ Typ (V): 6.8; P Max (W): 0.5

## Sheet ext_supply.SchDoc
size A3; SheetNumber: 11; SheetTotal: 15; SheetDescription: External Supply
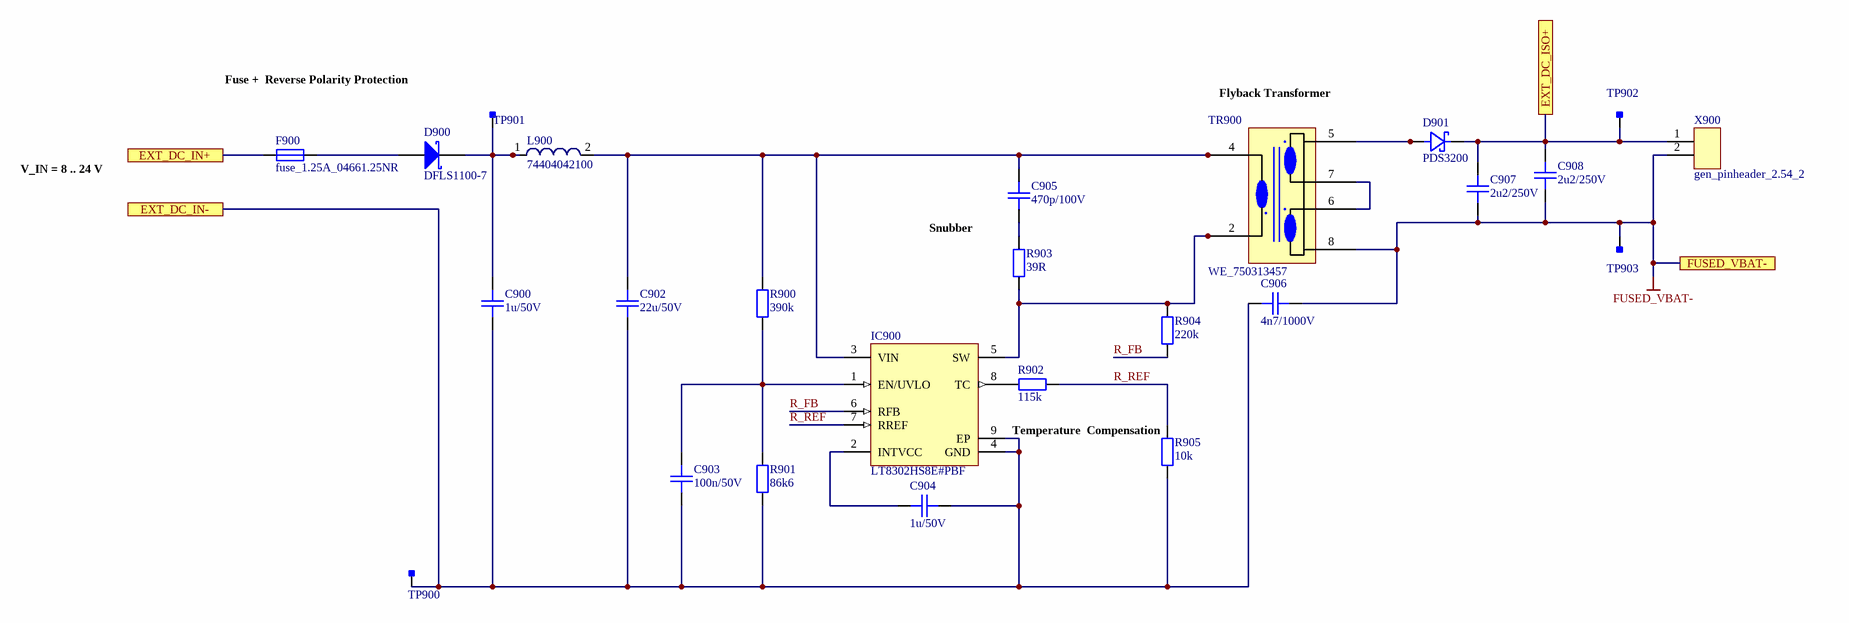
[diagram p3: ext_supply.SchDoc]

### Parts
C900  1u/50V  [CAPC2012X14N]
C902  22u/50V  [CAPC2220(5750)230_N]
C903  100n/50V  [CAPC1608X08N]
C904  1u/50V  [CAPC2012X14N]
C905  470p/100V  [CAPC2012X14N]
C906  4n7/1000V  [CAPC4532X16N]
C907  2u2/250V  [CAPC2220(5750)230_N]
C908  2u2/250V  [CAPC2220(5750)230_N]
D900  DFLS1100-7  [DIOD-POWERDI123-2_V]
D901  PDS3200  [PowerDI5]
F900  fuse_1.25A_04661.25NR  [LITTLEFUSE_466]
IC900  LT8302HS8E#PBF  [LT-S8E-8_V]
L900  74404042100  [WE-LQS 4018]
R900  390k  [RESC1608X05N]
R901  86k6  [RESC1608X05N]
R902  115k  [RESC1608X05N]
R903  39R  [RESC2012X05N]
R904  220k  [RESC1608X05N]
R905  10k  [RESC1608X05N]
TP900  Testpoint_Square  [Testpoint_S1]  (value not drawn)  (no BOM)
TP901  Testpoint_Square  [Testpoint_S1]  (value not drawn)  (no BOM)
TP902  Testpoint_Square  [Testpoint_S1]  (value not drawn)  (no BOM)
TP903  Testpoint_Square  [Testpoint_S1]  (value not drawn)  (no BOM)
TR900  WE_750313457  [WE_750313457]
X900  gen_pinheader_2.54_2  [Pinheader_2.54_2]

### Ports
EXT_DC_IN+, EXT_DC_IN-, EXT_DC_ISO+, FUSED_VBAT-

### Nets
FUSED_VBAT-: C906.2 C907.1 C908.1 TP903.1 TR900.8 X900.2 ; port FUSED_VBAT-
EXT_DC_IN+: F900.1 ; port EXT_DC_IN+
EXT_DC_IN-: C900.1 C902.1 C903.1 C904.1 C906.1 IC900.4(GND) IC900.9(EP) R901.1 R905.1 TP900.1 ; port EXT_DC_IN-
EXT_DC_ISO+: C907.2 C908.2 D901.1(C) TP902.1 X900.1 ; port EXT_DC_ISO+
R_FB: IC900.6(RFB) R904.1
R_REF: IC900.7(RREF) R902.2 R905.2
NetC900_2: C900.2 D900.2(K) L900.1 TP901.1
NetC902_2: C902.2 C905.2 IC900.3(VIN) L900.2 R900.2 TR900.3 TR900.4
NetC903_2: C903.2 IC900.1(EN/UVLO) R900.1 R901.2
NetC904_2: C904.2 IC900.2(INTVCC)
NetC905_1: C905.1 R903.2
NetD900_1: D900.1(A) F900.2
NetD901_2: D901.2(A) D901.3(A) TR900.5
NetIC900_5: IC900.5(SW) R903.1 R904.2 TR900.1 TR900.2
NetIC900_8: IC900.8(TC) R902.1
NetTR900_6: TR900.6 TR900.7

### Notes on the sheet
- Fuse +
  Reverse Polarity Protection
- (near TR900) Flyback Transformer
- V_IN = 8 .. 24 V
- Snubber
- (near R905) Temperature
  Compensation

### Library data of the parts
C900 C904 = gen_C_ceramic_1u_50V_X7R_0805: MLCC; Capacitance: 1u; Rated Voltage: 50V; Dielectric: X7R; Case EIA: 0805; Case Metric: 2012; Automotive Qualified: True; Tolerance: ± 10%; AVT Set: x
C902 = gen_C_ceramic_22u_50V_X7R_2220_stacked: MLCC; Capacitance: 22u; Rated Voltage: 50V; Dielectric: X7R; Case EIA: 2220; Case Metric: 5750; Automotive Qualified: True
C903 = gen_C_ceramic_100n_50V_X7R_0603: MLCC; Capacitance: 100n; Rated Voltage: 50V; Dielectric: X7R; Case EIA: 0603; Case Metric: 1608; PnP Package: C_0603_10; PnP Value: 100n/50V/X7R; PnP equipped: x; Automotive Qualified: True
C905 = gen_C_ceramic_470p_100V_X7R_0805: MLCC; Capacitance: 470p; Rated Voltage: 100V; Dielectric: X7R; Case EIA: 0805; Case Metric: 2012; Automotive Qualified: True
C906 = gen_C_ceramic_4n7_1000V_X7R_1812: MLCC; Capacitance: 4n7; Rated Voltage: 1000V; Dielectric: X7R; Case EIA: 1812; Case Metric: 4532; Automotive Qualified: True
C907 C908 = gen_C_ceramic_2u2_250V_X7R_2220: MLCC; Capacitance: 2u2; Rated Voltage: 250V; Dielectric: X7R; Case EIA: 2220; Case Metric: 5750; Automotive Qualified: True
D900 = CMP-2000-05099-1: 1 A High Voltage Schottky Barrier Rectifier, 0.62 V, -55 to 175 degC, 2- Pin POWERDI123, Pb-Free, Tape and Reel; Manufacturer: Diodes Inc; Average Rectified Current-Max: 1A; Peak Current-Max: 40A; Forward Voltage: 0.77V; Reverse Current-Max: 1µA; Reverse Voltage-Max [Vrrm]: 100V
D901 = PDS3200-13: Schottky Diode 3A 200V 780mV; Manufacturer: DIODES Inc; Automotive Qualified: True
F900 = fuse_1.25A_04661.25NR: Fuse, Surface Mount, 466 Series, 1.25 A, 63 VAC, 63 VDC, Very Fast Acting, 1206; Manufacturer: Littlefuse; Automotive Qualified: False
IC900 = CMP-0492-02715-1: Micropower No-Opto Isolated Flyback Converter, 2.8 to 42 V, -40 to 150 degC, 8-Pin SOIC (S8E), RoHS, Tube; PartNumber: LT8302; Output Current: 3.6 A; Number of Outputs: 1; VIN Min: 2.8 V; VIN Max: 42 V
L900 = CMP-1354-00028-1: WE-LQS SMD Power Inductor, L=10 µH; Manufacturer: Wuerth Elektronik; Inductance: 10 ÂµH
R900 = gen_R_390k_0603: SMD Resistor 390k 0603; Tolerance: 1%; Power: 0.1W; Case EIA: 0603; Case Metric: 1608; Maximum Working Voltage: 75V; PnP Package: R_0603; Automotive Qualified: True
R901 = gen_R_86k6_0603: SMD Resistor 86k6 0603; Tolerance: 1%; Power: 0.1W; Case EIA: 0603; Case Metric: 1608; Maximum Working Voltage: 75V; PnP Package: R_0603; Automotive Qualified: True
R902 = gen_R_115k_0603: SMD Resistor 115k 0603; Tolerance: 1%; Power: 0.1W; Case EIA: 0603; Case Metric: 1608; Maximum Working Voltage: 75V; PnP Package: R_0603; Automotive Qualified: True
R903 = gen_R_39R_0805: SMD Resistor 39R 0805; Tolerance: 1%; Power: 0.125W; Case EIA: 0805; Case Metric: 2012; Maximum Working Voltage: 150V; PnP Package: R_0805; Automotive Qualified: True
R904 = gen_R_220k_0603: SMD Resistor 220k 0603; Tolerance: 1%; Power: 0.1W; Case EIA: 0603; Case Metric: 1608; Maximum Working Voltage: 75V; PnP Package: R_0603; Automotive Qualified: False
R905 = gen_R_10k_0603: SMD Resistor 10k 0603; Tolerance: 1%; Power: 0.1W; Case EIA: 0603; Case Metric: 1608; Maximum Working Voltage: 75V; PnP Package: R_0603; Automotive Qualified: True
TP900-TP903 = Testpoint_Square: Testpoint, square
TR900 = WE_750313457: MID-FLYLT Flyback Transformers for Linear Technology; Manufacturer: Würth Elektronik; Automotive Qualified: False
X900 = gen_pinheader_2.54_2: Standard Pinheader, THD, gerade, 2.54mm; Circuits: 2; Rated Voltage: 250V; Rated Current: 3A; Automotive Qualified: False

## Sheet connectors.SchDoc
size A3; SheetNumber: 10; SheetTotal: 15; SheetDescription: Connectors
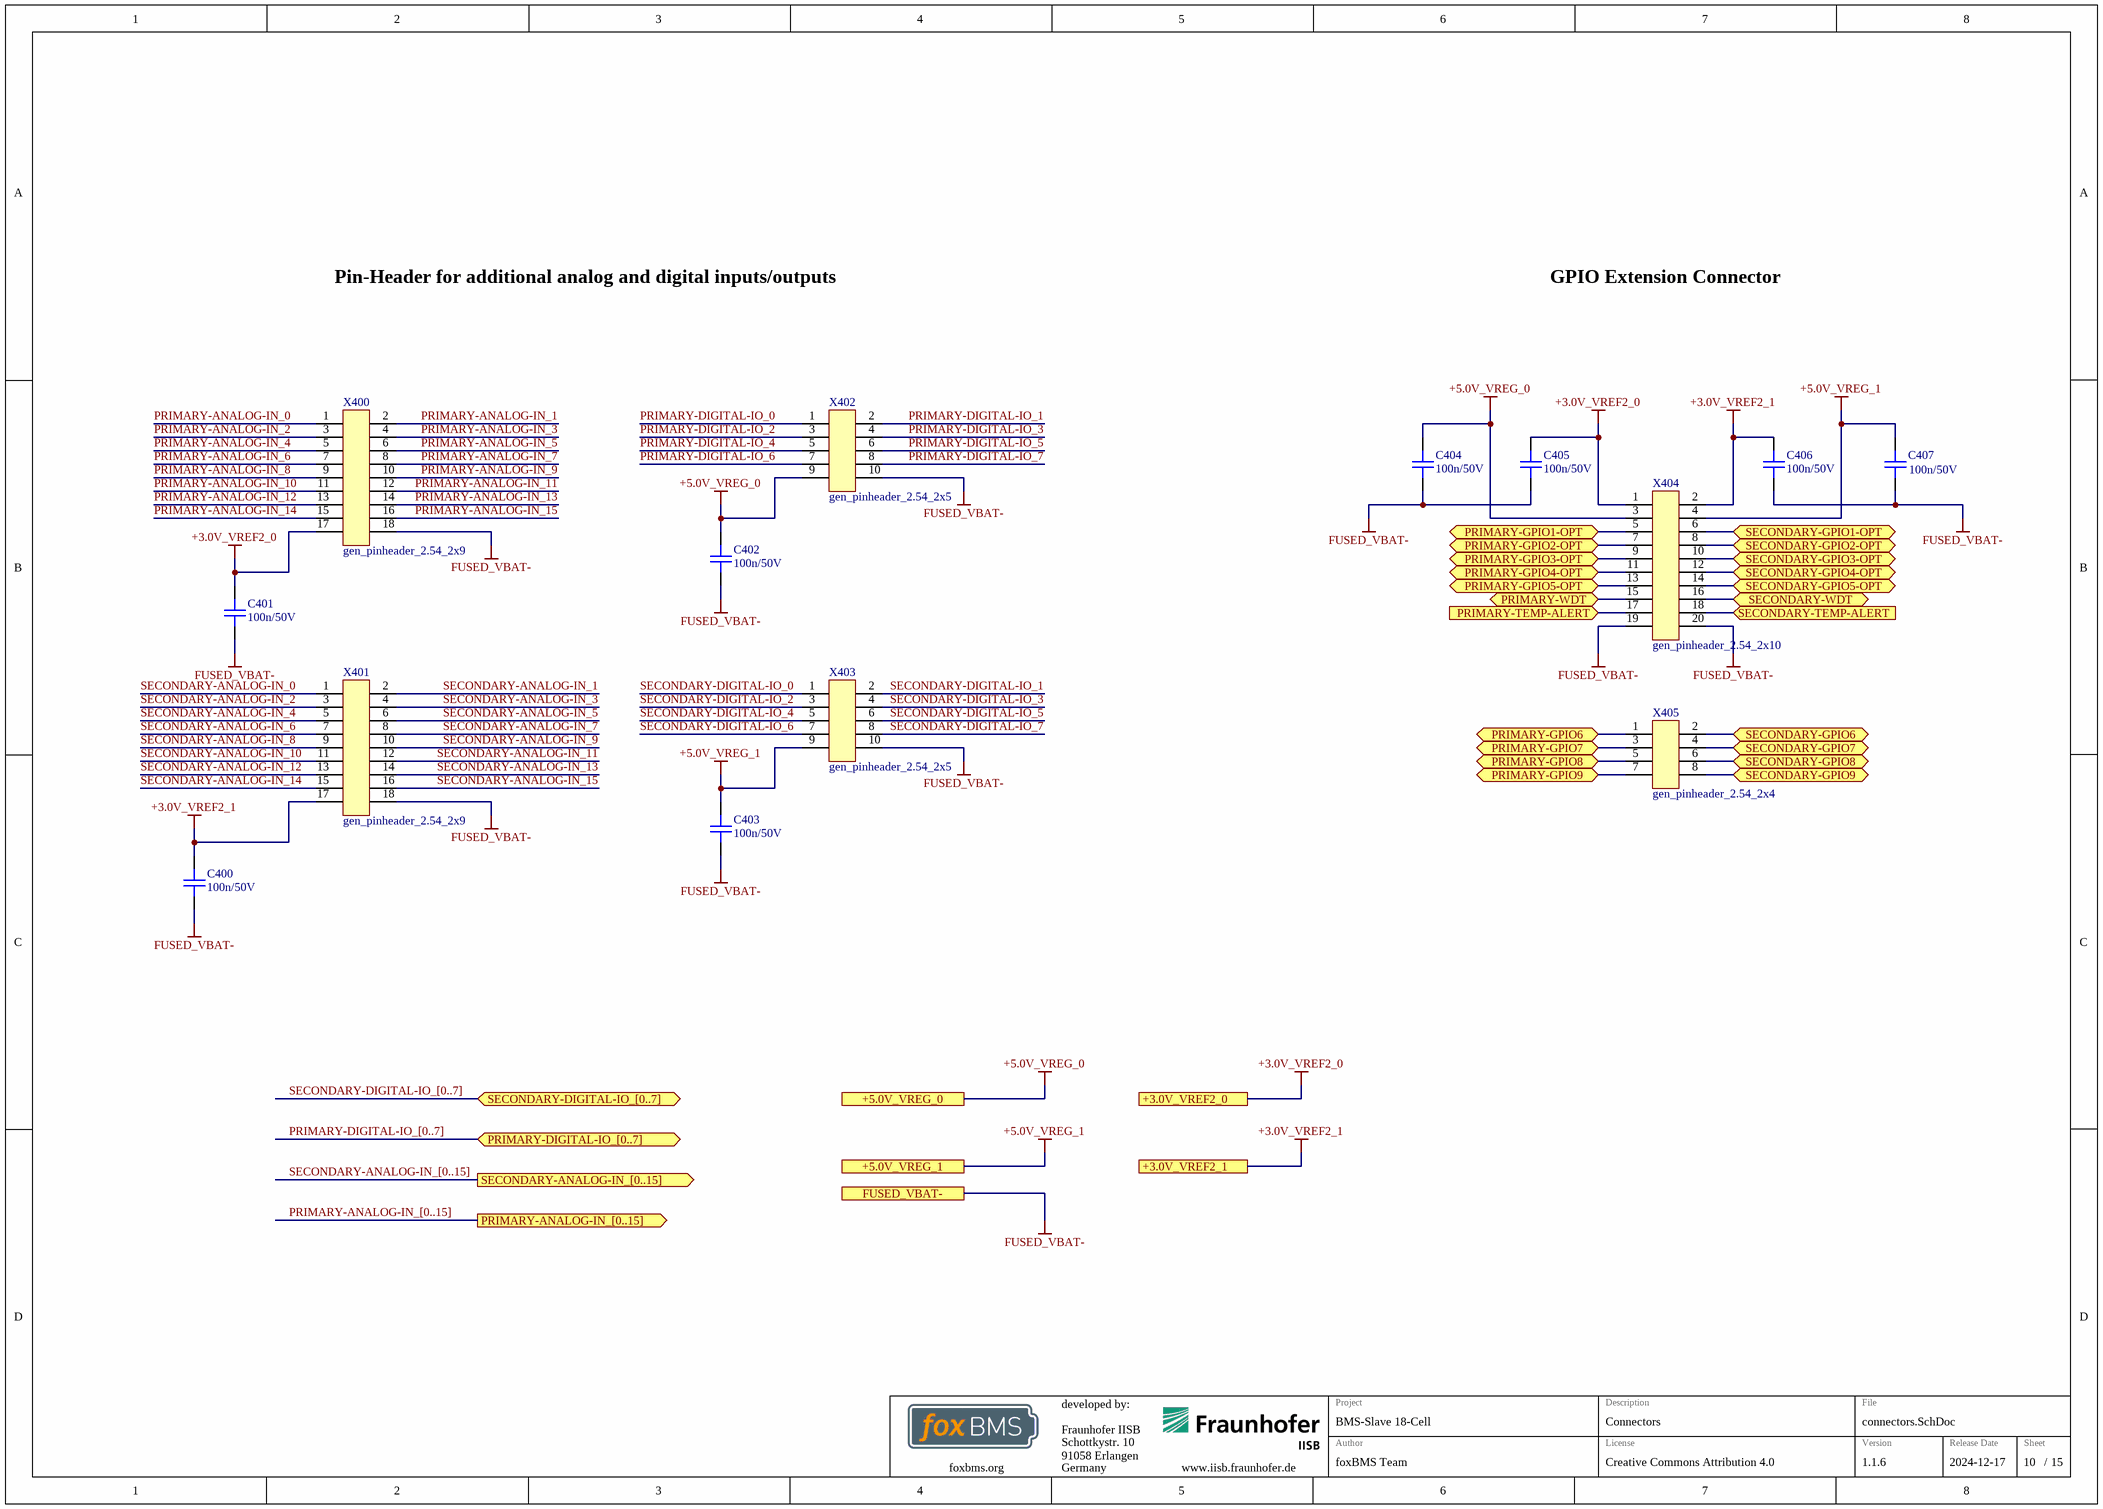
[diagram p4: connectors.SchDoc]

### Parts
C400  100n/50V  [CAPC1608X08N]
C401  100n/50V  [CAPC1608X08N]
C402  100n/50V  [CAPC1608X08N]
C403  100n/50V  [CAPC1608X08N]
C404  100n/50V  [CAPC1608X08N]
C405  100n/50V  [CAPC1608X08N]
C406  100n/50V  [CAPC1608X08N]
C407  100n/50V  [CAPC1608X08N]
X400  gen_pinheader_2.54_2x9  [Pinheader_2.54_2x9]
X401  gen_pinheader_2.54_2x9  [Pinheader_2.54_2x9]
X402  gen_pinheader_2.54_2x5  [Pinheader_2.54_2x5]
X403  gen_pinheader_2.54_2x5  [Pinheader_2.54_2x5]
X404  gen_pinheader_2.54_2x10  [Pinheader_2.54_2x10]
X405  gen_pinheader_2.54_2x4  [Pinheader_2.54_2x4]

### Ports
+3.0V_VREF2_0, +3.0V_VREF2_1, +5.0V_VREG_0, +5.0V_VREG_1, FUSED_VBAT-, PRIMARY-ANALOG-IN_[0..15] (out), PRIMARY-DIGITAL-IO_[0..7] (bidir), PRIMARY-GPIO1-OPT (bidir), PRIMARY-GPIO2-OPT (bidir), PRIMARY-GPIO3-OPT (bidir), PRIMARY-GPIO4-OPT (bidir), PRIMARY-GPIO5-OPT (bidir), PRIMARY-GPIO6 (bidir), PRIMARY-GPIO7 (bidir), PRIMARY-GPIO8 (bidir), PRIMARY-GPIO9 (bidir), PRIMARY-TEMP-ALERT (in), PRIMARY-WDT (bidir), SECONDARY-ANALOG-IN_[0..15] (out), SECONDARY-DIGITAL-IO_[0..7] (bidir), SECONDARY-GPIO1-OPT (bidir), SECONDARY-GPIO2-OPT (bidir), SECONDARY-GPIO3-OPT (bidir), SECONDARY-GPIO4-OPT (bidir), SECONDARY-GPIO5-OPT (bidir), SECONDARY-GPIO6 (bidir), SECONDARY-GPIO7 (bidir), SECONDARY-GPIO8 (bidir), SECONDARY-GPIO9 (bidir), SECONDARY-TEMP-ALERT (in), SECONDARY-WDT (bidir)

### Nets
+3.0V_VREF2_0: C401.2 C405.2 X400.17 X404.1 ; port +3.0V_VREF2_0  [project net +3.0V_VREF2]
+3.0V_VREF2_1: C400.2 C406.2 X401.17 X404.2 ; port +3.0V_VREF2_1  [project net +3.0V_VREF2]
+5.0V_VREG_0: C402.2 C404.2 X402.9 X404.3 ; port +5.0V_VREG_0  [project net +5.0V_VREG]
+5.0V_VREG_1: C403.2 C407.2 X403.9 X404.4 ; port +5.0V_VREG_1  [project net +5.0V_VREG]
FUSED_VBAT-: C400.1 C401.1 C402.1 C403.1 C404.1 C405.1 C406.1 C407.1 X400.18 X401.18 X402.10 X403.10 X404.19 X404.20 ; port FUSED_VBAT-
PRIMARY-ANALOG-IN_0: X400.1
PRIMARY-ANALOG-IN_1: X400.2
PRIMARY-ANALOG-IN_2: X400.3
PRIMARY-ANALOG-IN_3: X400.4
PRIMARY-ANALOG-IN_4: X400.5
PRIMARY-ANALOG-IN_5: X400.6
PRIMARY-ANALOG-IN_6: X400.7
PRIMARY-ANALOG-IN_7: X400.8
PRIMARY-ANALOG-IN_8: X400.9
PRIMARY-ANALOG-IN_9: X400.10
PRIMARY-ANALOG-IN_10: X400.11
PRIMARY-ANALOG-IN_11: X400.12
PRIMARY-ANALOG-IN_12: X400.13
PRIMARY-ANALOG-IN_13: X400.14
PRIMARY-ANALOG-IN_14: X400.15
PRIMARY-ANALOG-IN_15: X400.16
PRIMARY-DIGITAL-IO_0: X402.1
PRIMARY-DIGITAL-IO_1: X402.2
PRIMARY-DIGITAL-IO_2: X402.3
PRIMARY-DIGITAL-IO_3: X402.4
PRIMARY-DIGITAL-IO_4: X402.5
PRIMARY-DIGITAL-IO_5: X402.6
PRIMARY-DIGITAL-IO_6: X402.7
PRIMARY-DIGITAL-IO_7: X402.8
PRIMARY-GPIO1-OPT: X404.5 ; port PRIMARY-GPIO1-OPT
PRIMARY-GPIO2-OPT: X404.7 ; port PRIMARY-GPIO2-OPT
PRIMARY-GPIO3-OPT: X404.9 ; port PRIMARY-GPIO3-OPT
PRIMARY-GPIO4-OPT: X404.11 ; port PRIMARY-GPIO4-OPT
PRIMARY-GPIO5-OPT: X404.13 ; port PRIMARY-GPIO5-OPT
PRIMARY-GPIO6: X405.1 ; port PRIMARY-GPIO6
PRIMARY-GPIO7: X405.3 ; port PRIMARY-GPIO7
PRIMARY-GPIO8: X405.5 ; port PRIMARY-GPIO8
PRIMARY-GPIO9: X405.7 ; port PRIMARY-GPIO9
PRIMARY-TEMP-ALERT: X404.17 ; port PRIMARY-TEMP-ALERT
PRIMARY-WDT: X404.15 ; port PRIMARY-WDT
SECONDARY-ANALOG-IN_0: X401.1
SECONDARY-ANALOG-IN_1: X401.2
SECONDARY-ANALOG-IN_2: X401.3
SECONDARY-ANALOG-IN_3: X401.4
SECONDARY-ANALOG-IN_4: X401.5
SECONDARY-ANALOG-IN_5: X401.6
SECONDARY-ANALOG-IN_6: X401.7
SECONDARY-ANALOG-IN_7: X401.8
SECONDARY-ANALOG-IN_8: X401.9
SECONDARY-ANALOG-IN_9: X401.10
SECONDARY-ANALOG-IN_10: X401.11
SECONDARY-ANALOG-IN_11: X401.12
SECONDARY-ANALOG-IN_12: X401.13
SECONDARY-ANALOG-IN_13: X401.14
SECONDARY-ANALOG-IN_14: X401.15
SECONDARY-ANALOG-IN_15: X401.16
SECONDARY-DIGITAL-IO_0: X403.1
SECONDARY-DIGITAL-IO_1: X403.2
SECONDARY-DIGITAL-IO_2: X403.3
SECONDARY-DIGITAL-IO_3: X403.4
SECONDARY-DIGITAL-IO_4: X403.5
SECONDARY-DIGITAL-IO_5: X403.6
SECONDARY-DIGITAL-IO_6: X403.7
SECONDARY-DIGITAL-IO_7: X403.8
SECONDARY-GPIO1-OPT: X404.6 ; port SECONDARY-GPIO1-OPT
SECONDARY-GPIO2-OPT: X404.8 ; port SECONDARY-GPIO2-OPT
SECONDARY-GPIO3-OPT: X404.10 ; port SECONDARY-GPIO3-OPT
SECONDARY-GPIO4-OPT: X404.12 ; port SECONDARY-GPIO4-OPT
SECONDARY-GPIO5-OPT: X404.14 ; port SECONDARY-GPIO5-OPT
SECONDARY-GPIO6: X405.2 ; port SECONDARY-GPIO6
SECONDARY-GPIO7: X405.4 ; port SECONDARY-GPIO7
SECONDARY-GPIO8: X405.6 ; port SECONDARY-GPIO8
SECONDARY-GPIO9: X405.8 ; port SECONDARY-GPIO9
SECONDARY-TEMP-ALERT: X404.18 ; port SECONDARY-TEMP-ALERT
SECONDARY-WDT: X404.16 ; port SECONDARY-WDT

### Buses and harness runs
bus PRIMARY-ANALOG-IN_[0..15] = port PRIMARY-ANALOG-IN_[0..15]
bus PRIMARY-DIGITAL-IO_[0..7] = port PRIMARY-DIGITAL-IO_[0..7]
bus SECONDARY-ANALOG-IN_[0..15] = port SECONDARY-ANALOG-IN_[0..15]
bus SECONDARY-DIGITAL-IO_[0..7] = port SECONDARY-DIGITAL-IO_[0..7]

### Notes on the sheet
- Pin-Header for additional analog and digital inputs/outputs
- GPIO Extension Connector

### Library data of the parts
C400-C407 = gen_C_ceramic_100n_50V_X7R_0603: as C903 on sheet ext_supply
X400 X401 = gen_pinheader_2.54_2x9: Standard Pinheader, THD, gerade, 2.54mm, 2-reihig; Circuits: 18; Rated Voltage: 250V; Rated Current: 3A; Automotive Qualified: False
X402 X403 = gen_pinheader_2.54_2x5: Standard Pinheader, THD, gerade, 2.54mm, 2-reihig; Circuits: 10; Rated Voltage: 250V; Rated Current: 3A; Automotive Qualified: False
X404 = gen_pinheader_2.54_2x10: Standard Pinheader, THD, gerade, 2.54mm, 2-reihig; Circuits: 20; Rated Voltage: 250V; Rated Current: 3A; Automotive Qualified: False
X405 = gen_pinheader_2.54_2x4: Standard Pinheader, THD, gerade, 2.54mm, 2-reihig; Circuits: 8; Rated Voltage: 250V; Rated Current: 3A; Automotive Qualified: False

## Sheet feedback.SchDoc
size A3; SheetNumber: 6; SheetTotal: 15; SheetDescription: Balancing Feedback
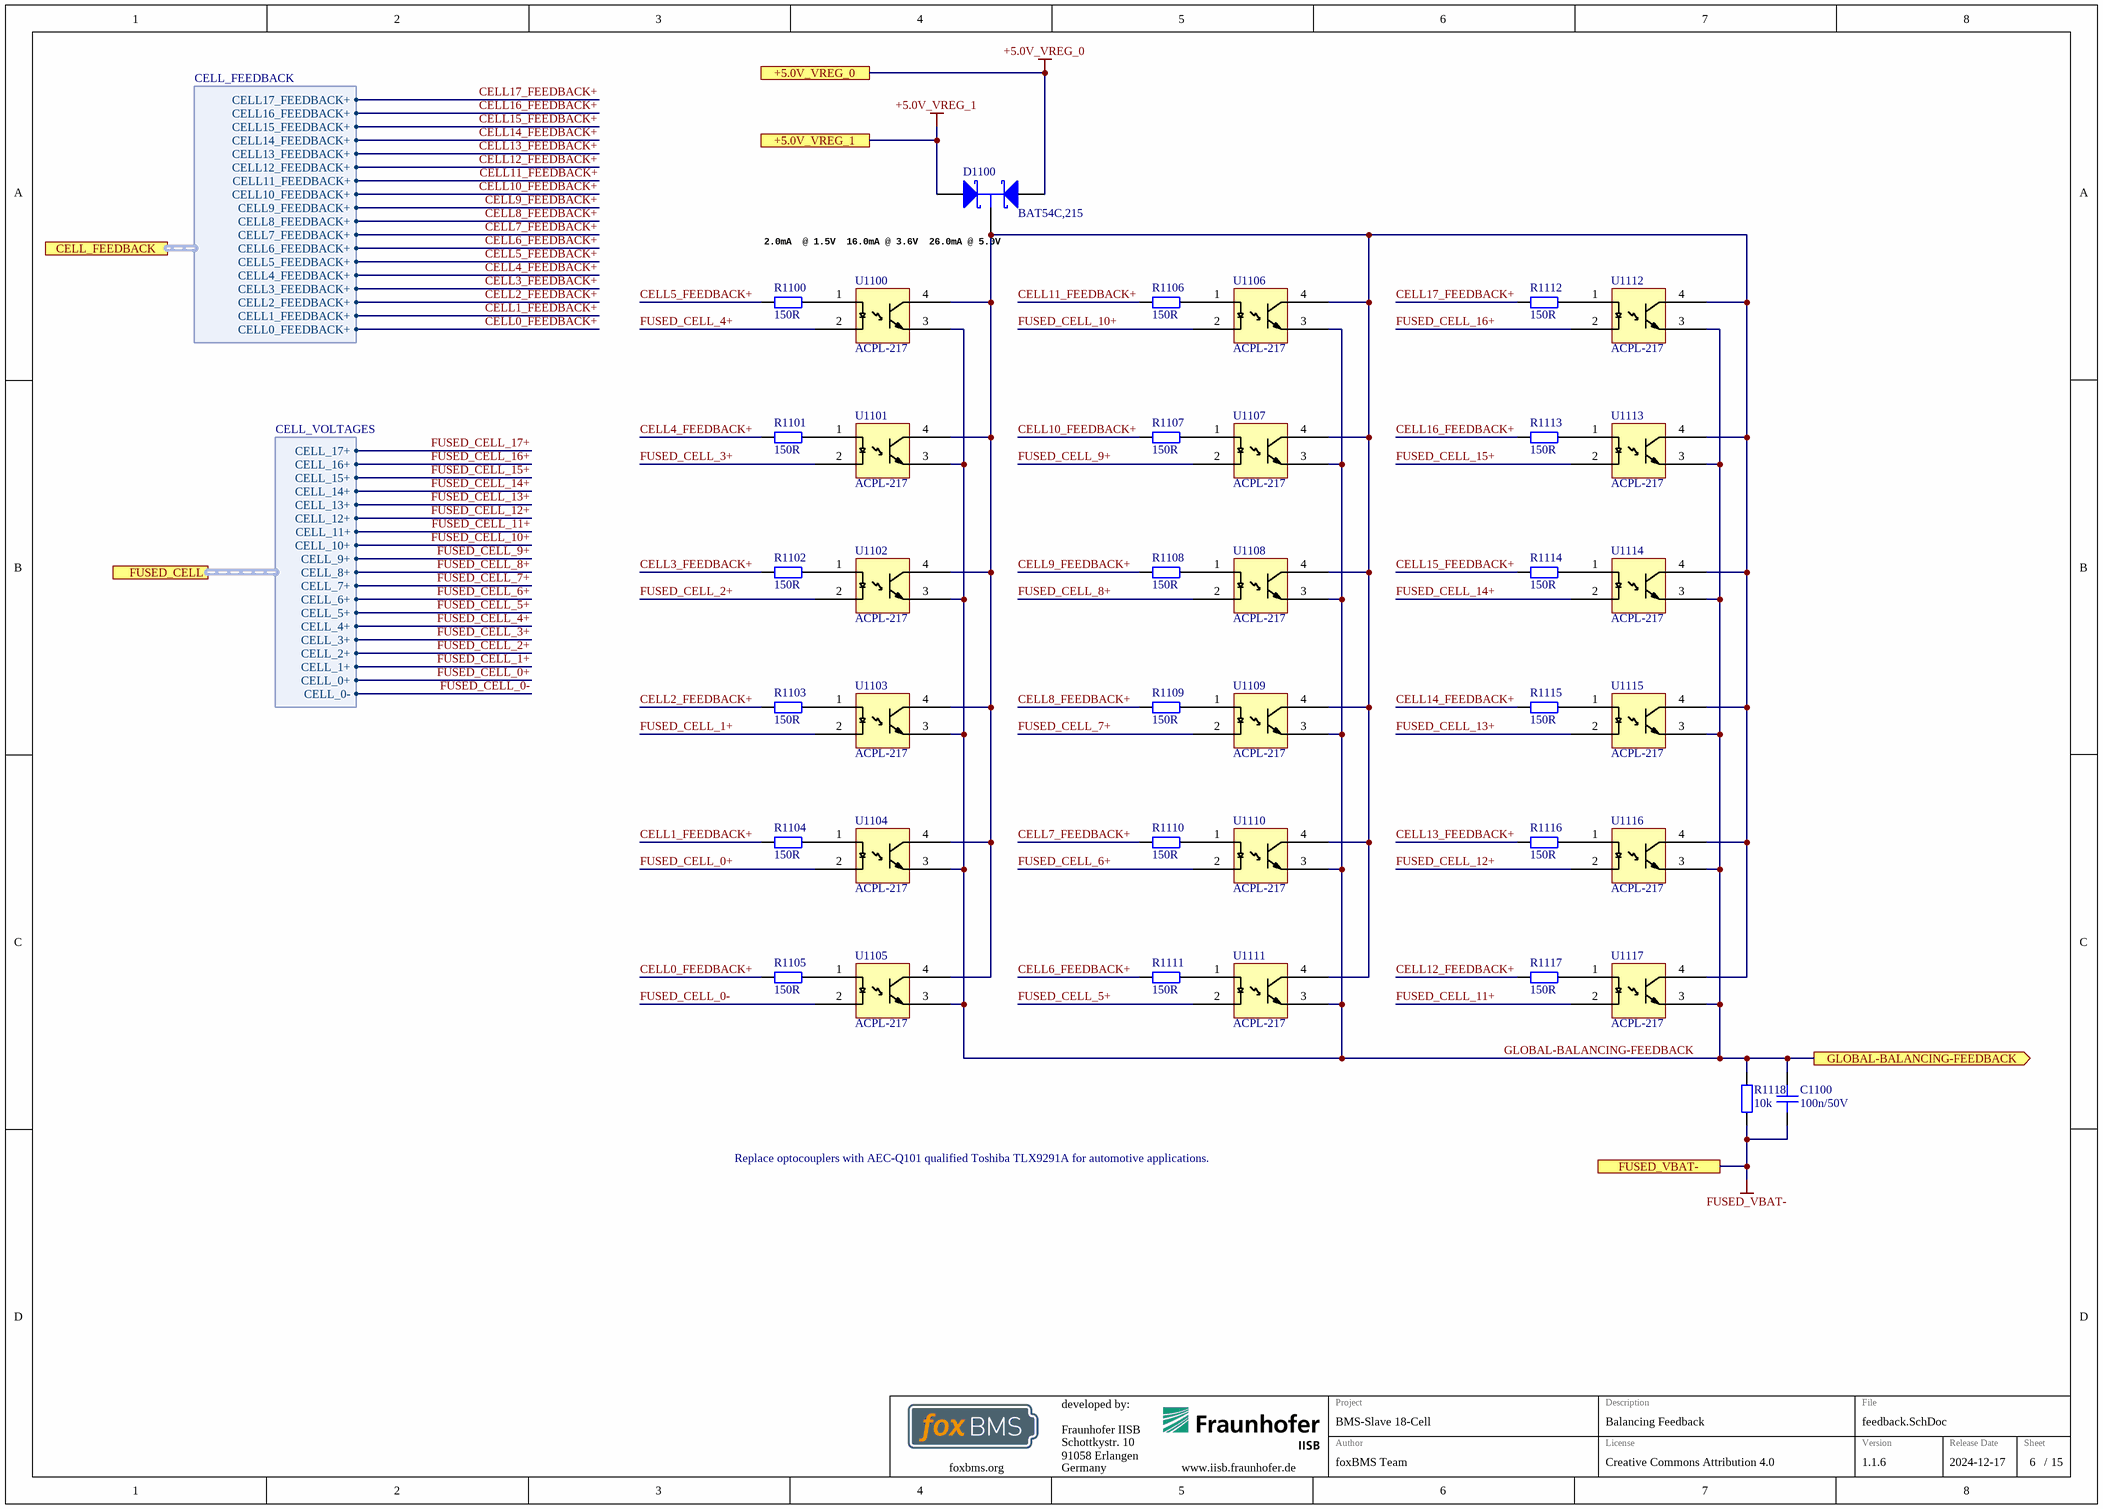
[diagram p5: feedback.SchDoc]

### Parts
C1100  100n/50V  [CAPC1608X08N]
D1100  BAT54C,215  [NXP-SOT23-3_V]
R1100  150R  [RESC1608X05N]
R1101  150R  [RESC1608X05N]
R1102  150R  [RESC1608X05N]
R1103  150R  [RESC1608X05N]
R1104  150R  [RESC1608X05N]
R1105  150R  [RESC1608X05N]
R1106  150R  [RESC1608X05N]
R1107  150R  [RESC1608X05N]
R1108  150R  [RESC1608X05N]
R1109  150R  [RESC1608X05N]
R1110  150R  [RESC1608X05N]
R1111  150R  [RESC1608X05N]
R1112  150R  [RESC1608X05N]
R1113  150R  [RESC1608X05N]
R1114  150R  [RESC1608X05N]
R1115  150R  [RESC1608X05N]
R1116  150R  [RESC1608X05N]
R1117  150R  [RESC1608X05N]
R1118  10k  [RESC1608X05N]
U1100  ACPL-217  [SOIC127P700X220-4N]
U1101  ACPL-217  [SOIC127P700X220-4N]
U1102  ACPL-217  [SOIC127P700X220-4N]
U1103  ACPL-217  [SOIC127P700X220-4N]
U1104  ACPL-217  [SOIC127P700X220-4N]
U1105  ACPL-217  [SOIC127P700X220-4N]
U1106  ACPL-217  [SOIC127P700X220-4N]
U1107  ACPL-217  [SOIC127P700X220-4N]
U1108  ACPL-217  [SOIC127P700X220-4N]
U1109  ACPL-217  [SOIC127P700X220-4N]
U1110  ACPL-217  [SOIC127P700X220-4N]
U1111  ACPL-217  [SOIC127P700X220-4N]
U1112  ACPL-217  [SOIC127P700X220-4N]
U1113  ACPL-217  [SOIC127P700X220-4N]
U1114  ACPL-217  [SOIC127P700X220-4N]
U1115  ACPL-217  [SOIC127P700X220-4N]
U1116  ACPL-217  [SOIC127P700X220-4N]
U1117  ACPL-217  [SOIC127P700X220-4N]

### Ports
+5.0V_VREG_0, +5.0V_VREG_1, CELL_FEEDBACK (harness CELL_FEEDBACK), FUSED_CELL (harness CELL_VOLTAGES), FUSED_VBAT-, GLOBAL-BALANCING-FEEDBACK (out)

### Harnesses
CELL_VOLTAGES: CELL_0-, CELL_0+, CELL_1+, CELL_10+, CELL_11+, CELL_12+, CELL_13+, CELL_14+, CELL_15+, CELL_16+, CELL_17+, CELL_2+, CELL_3+, CELL_4+, CELL_5+, CELL_6+, CELL_7+, CELL_8+, CELL_9+
CELL_FEEDBACK: CELL11_FEEDBACK+, CELL10_FEEDBACK+, CELL9_FEEDBACK+, CELL8_FEEDBACK+, CELL7_FEEDBACK+, CELL6_FEEDBACK+, CELL5_FEEDBACK+, CELL4_FEEDBACK+, CELL3_FEEDBACK+, CELL2_FEEDBACK+, CELL1_FEEDBACK+, CELL0_FEEDBACK+, CELL12_FEEDBACK+, CELL13_FEEDBACK+, CELL14_FEEDBACK+, CELL15_FEEDBACK+, CELL16_FEEDBACK+, CELL17_FEEDBACK+

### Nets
+5.0V_VREG_0: D1100.2(A) ; port +5.0V_VREG_0  [project net +5.0V_VREG]
+5.0V_VREG_1: D1100.1(A) ; port +5.0V_VREG_1  [project net +5.0V_VREG]
FUSED_VBAT-: C1100.1 R1118.2 ; port FUSED_VBAT-
CELL0_FEEDBACK+: R1105.1 ; port CELL_FEEDBACK.CELL0_FEEDBACK+  [project net CELL_FEEDBACK.CELL0_FEEDBACK+]
CELL1_FEEDBACK+: R1104.1 ; port CELL_FEEDBACK.CELL1_FEEDBACK+  [project net CELL_FEEDBACK.CELL1_FEEDBACK+]
CELL2_FEEDBACK+: R1103.1 ; port CELL_FEEDBACK.CELL2_FEEDBACK+  [project net CELL_FEEDBACK.CELL2_FEEDBACK+]
CELL3_FEEDBACK+: R1102.1 ; port CELL_FEEDBACK.CELL3_FEEDBACK+  [project net CELL_FEEDBACK.CELL3_FEEDBACK+]
CELL4_FEEDBACK+: R1101.1 ; port CELL_FEEDBACK.CELL4_FEEDBACK+  [project net CELL_FEEDBACK.CELL4_FEEDBACK+]
CELL5_FEEDBACK+: R1100.1 ; port CELL_FEEDBACK.CELL5_FEEDBACK+  [project net CELL_FEEDBACK.CELL5_FEEDBACK+]
CELL6_FEEDBACK+: R1111.1 ; port CELL_FEEDBACK.CELL6_FEEDBACK+  [project net CELL_FEEDBACK.CELL6_FEEDBACK+]
CELL7_FEEDBACK+: R1110.1 ; port CELL_FEEDBACK.CELL7_FEEDBACK+  [project net CELL_FEEDBACK.CELL7_FEEDBACK+]
CELL8_FEEDBACK+: R1109.1 ; port CELL_FEEDBACK.CELL8_FEEDBACK+  [project net CELL_FEEDBACK.CELL8_FEEDBACK+]
CELL9_FEEDBACK+: R1108.1 ; port CELL_FEEDBACK.CELL9_FEEDBACK+  [project net CELL_FEEDBACK.CELL9_FEEDBACK+]
CELL10_FEEDBACK+: R1107.1 ; port CELL_FEEDBACK.CELL10_FEEDBACK+  [project net CELL_FEEDBACK.CELL10_FEEDBACK+]
CELL11_FEEDBACK+: R1106.1 ; port CELL_FEEDBACK.CELL11_FEEDBACK+  [project net CELL_FEEDBACK.CELL11_FEEDBACK+]
CELL12_FEEDBACK+: R1117.1 ; port CELL_FEEDBACK.CELL12_FEEDBACK+  [project net CELL_FEEDBACK.CELL12_FEEDBACK+]
CELL13_FEEDBACK+: R1116.1 ; port CELL_FEEDBACK.CELL13_FEEDBACK+  [project net CELL_FEEDBACK.CELL13_FEEDBACK+]
CELL14_FEEDBACK+: R1115.1 ; port CELL_FEEDBACK.CELL14_FEEDBACK+  [project net CELL_FEEDBACK.CELL14_FEEDBACK+]
CELL15_FEEDBACK+: R1114.1 ; port CELL_FEEDBACK.CELL15_FEEDBACK+  [project net CELL_FEEDBACK.CELL15_FEEDBACK+]
CELL16_FEEDBACK+: R1113.1 ; port CELL_FEEDBACK.CELL16_FEEDBACK+  [project net CELL_FEEDBACK.CELL16_FEEDBACK+]
CELL17_FEEDBACK+: R1112.1 ; port CELL_FEEDBACK.CELL17_FEEDBACK+  [project net CELL_FEEDBACK.CELL17_FEEDBACK+]
FUSED_CELL_0+: U1104.2 ; port FUSED_CELL.CELL_0+  [project net FUSED_CELL.CELL_0+]
FUSED_CELL_0-: U1105.2 ; port FUSED_CELL.CELL_0-  [project net FUSED_CELL.CELL_0-]
FUSED_CELL_1+: U1103.2 ; port FUSED_CELL.CELL_1+  [project net FUSED_CELL.CELL_1+]
FUSED_CELL_2+: U1102.2 ; port FUSED_CELL.CELL_2+  [project net FUSED_CELL.CELL_2+]
FUSED_CELL_3+: U1101.2 ; port FUSED_CELL.CELL_3+  [project net FUSED_CELL.CELL_3+]
FUSED_CELL_4+: U1100.2 ; port FUSED_CELL.CELL_4+  [project net FUSED_CELL.CELL_4+]
FUSED_CELL_5+: U1111.2 ; port FUSED_CELL.CELL_5+  [project net FUSED_CELL.CELL_5+]
FUSED_CELL_6+: U1110.2 ; port FUSED_CELL.CELL_6+  [project net FUSED_CELL.CELL_6+]
FUSED_CELL_7+: U1109.2 ; port FUSED_CELL.CELL_7+  [project net FUSED_CELL.CELL_7+]
FUSED_CELL_8+: U1108.2 ; port FUSED_CELL.CELL_8+  [project net FUSED_CELL.CELL_8+]
FUSED_CELL_9+: U1107.2 ; port FUSED_CELL.CELL_9+  [project net FUSED_CELL.CELL_9+]
FUSED_CELL_10+: U1106.2 ; port FUSED_CELL.CELL_10+  [project net FUSED_CELL.CELL_10+]
FUSED_CELL_11+: U1117.2 ; port FUSED_CELL.CELL_11+  [project net FUSED_CELL.CELL_11+]
FUSED_CELL_12+: U1116.2 ; port FUSED_CELL.CELL_12+  [project net FUSED_CELL.CELL_12+]
FUSED_CELL_13+: U1115.2 ; port FUSED_CELL.CELL_13+  [project net FUSED_CELL.CELL_13+]
FUSED_CELL_14+: U1114.2 ; port FUSED_CELL.CELL_14+  [project net FUSED_CELL.CELL_14+]
FUSED_CELL_15+: U1113.2 ; port FUSED_CELL.CELL_15+  [project net FUSED_CELL.CELL_15+]
FUSED_CELL_16+: U1112.2 ; port FUSED_CELL.CELL_16+  [project net FUSED_CELL.CELL_16+]
GLOBAL-BALANCING-FEEDBACK: C1100.2 R1118.1 U1100.3 U1101.3 U1102.3 U1103.3 U1104.3 U1105.3 U1106.3 U1107.3 U1108.3 U1109.3 U1110.3 U1111.3 U1112.3 U1113.3 U1114.3 U1115.3 U1116.3 U1117.3 ; port GLOBAL-BALANCING-FEEDBACK  [project net GLOBAL-BAL-FB]
NetD1100_3: D1100.3(K) U1100.4 U1101.4 U1102.4 U1103.4 U1104.4 U1105.4 U1106.4 U1107.4 U1108.4 U1109.4 U1110.4 U1111.4 U1112.4 U1113.4 U1114.4 U1115.4 U1116.4 U1117.4
NetR1100_2: R1100.2 U1100.1
NetR1101_2: R1101.2 U1101.1
NetR1102_2: R1102.2 U1102.1
NetR1103_2: R1103.2 U1103.1
NetR1104_2: R1104.2 U1104.1
NetR1105_2: R1105.2 U1105.1
NetR1106_2: R1106.2 U1106.1
NetR1107_2: R1107.2 U1107.1
NetR1108_2: R1108.2 U1108.1
NetR1109_2: R1109.2 U1109.1
NetR1110_2: R1110.2 U1110.1
NetR1111_2: R1111.2 U1111.1
NetR1112_2: R1112.2 U1112.1
NetR1113_2: R1113.2 U1113.1
NetR1114_2: R1114.2 U1114.1
NetR1115_2: R1115.2 U1115.1
NetR1116_2: R1116.2 U1116.1
NetR1117_2: R1117.2 U1117.1

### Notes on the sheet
- (near D1100) 2.0mA  @ 1.5V
  16.0mA @ 3.6V
  26.0mA @ 5.0V
- Replace optocouplers with AEC-Q101 qualified Toshiba TLX9291A for automotive applications.

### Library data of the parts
C1100 = gen_C_ceramic_100n_50V_X7R_0603: as C903 on sheet ext_supply
D1100 = CMP-2000-04915-1: Schottky Barrier Diode, 30 V, 3-Pin SOT23, RoHS, Tape and Reel; Manufacturer: NXP Semiconductors; Forward Surge Current Ifsm Max: 600mA; Pin Configuration: 1A1,2A2,3comK; Package Version: Feb-16; Forward Voltage VF Max: 800mV; SMD Marking: L43/*W1; Diode Case Style: SOT-23; Reverse Recovery Time trr Typ: 5ns; Forward Current If(AV): 200mA; Reel Quantity: 3000; SVHC: NoSVHC(19-Dec-2012); No. of Pins: 3; Junction Temperature Tj Max: 125degC; Common Connection: Cathode; Repetitive Reverse Voltage Vrrm Max: 30V
R1100-R1117 = gen_R_150R_0603: SMD Resistor 150R 0603; Tolerance: 1%; Power: 0.1W; Case EIA: 0603; Case Metric: 1608; Maximum Working Voltage: 75V; PnP Package: R_0603; Automotive Qualified: True
R1118 = gen_R_10k_0603: as R905 on sheet ext_supply
U1100-U1117 = ACPL-217-56BE: Optocoupler, Transistor Output, 1 Channel; Manufacturer: Broadcom Limited; Automotive Qualified: False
